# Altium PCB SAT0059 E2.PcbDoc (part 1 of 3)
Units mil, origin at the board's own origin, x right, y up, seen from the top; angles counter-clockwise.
Board outline 3960.27 x 3100.03 mil, 6 copper layers (Top Layer, GND, Power, Inner Routing, GND 2, Bottom Layer), stack 59.2 mil thick; 276 components, 209 nets, 812 pads, 621 vias.
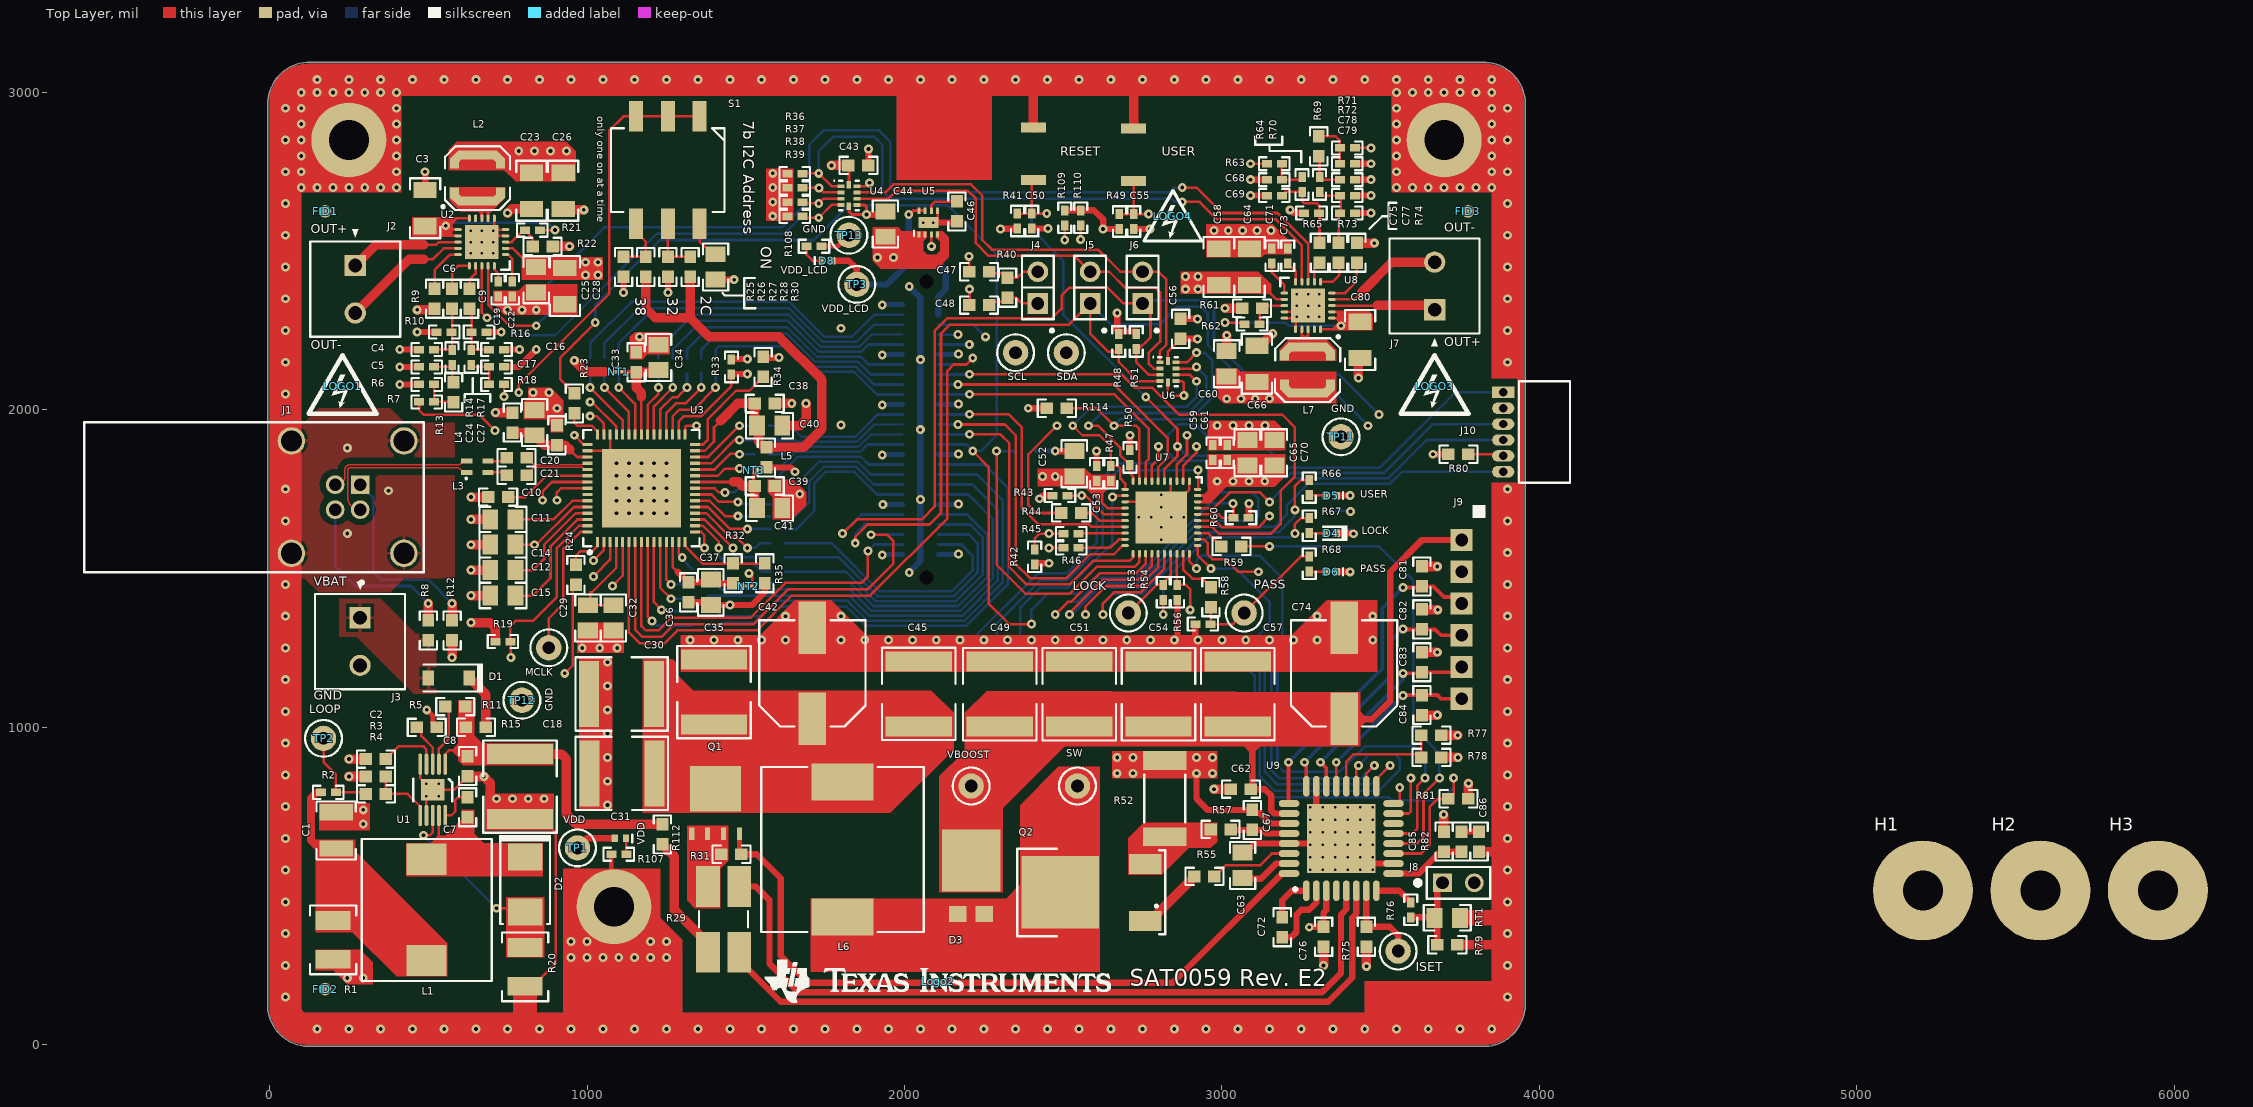
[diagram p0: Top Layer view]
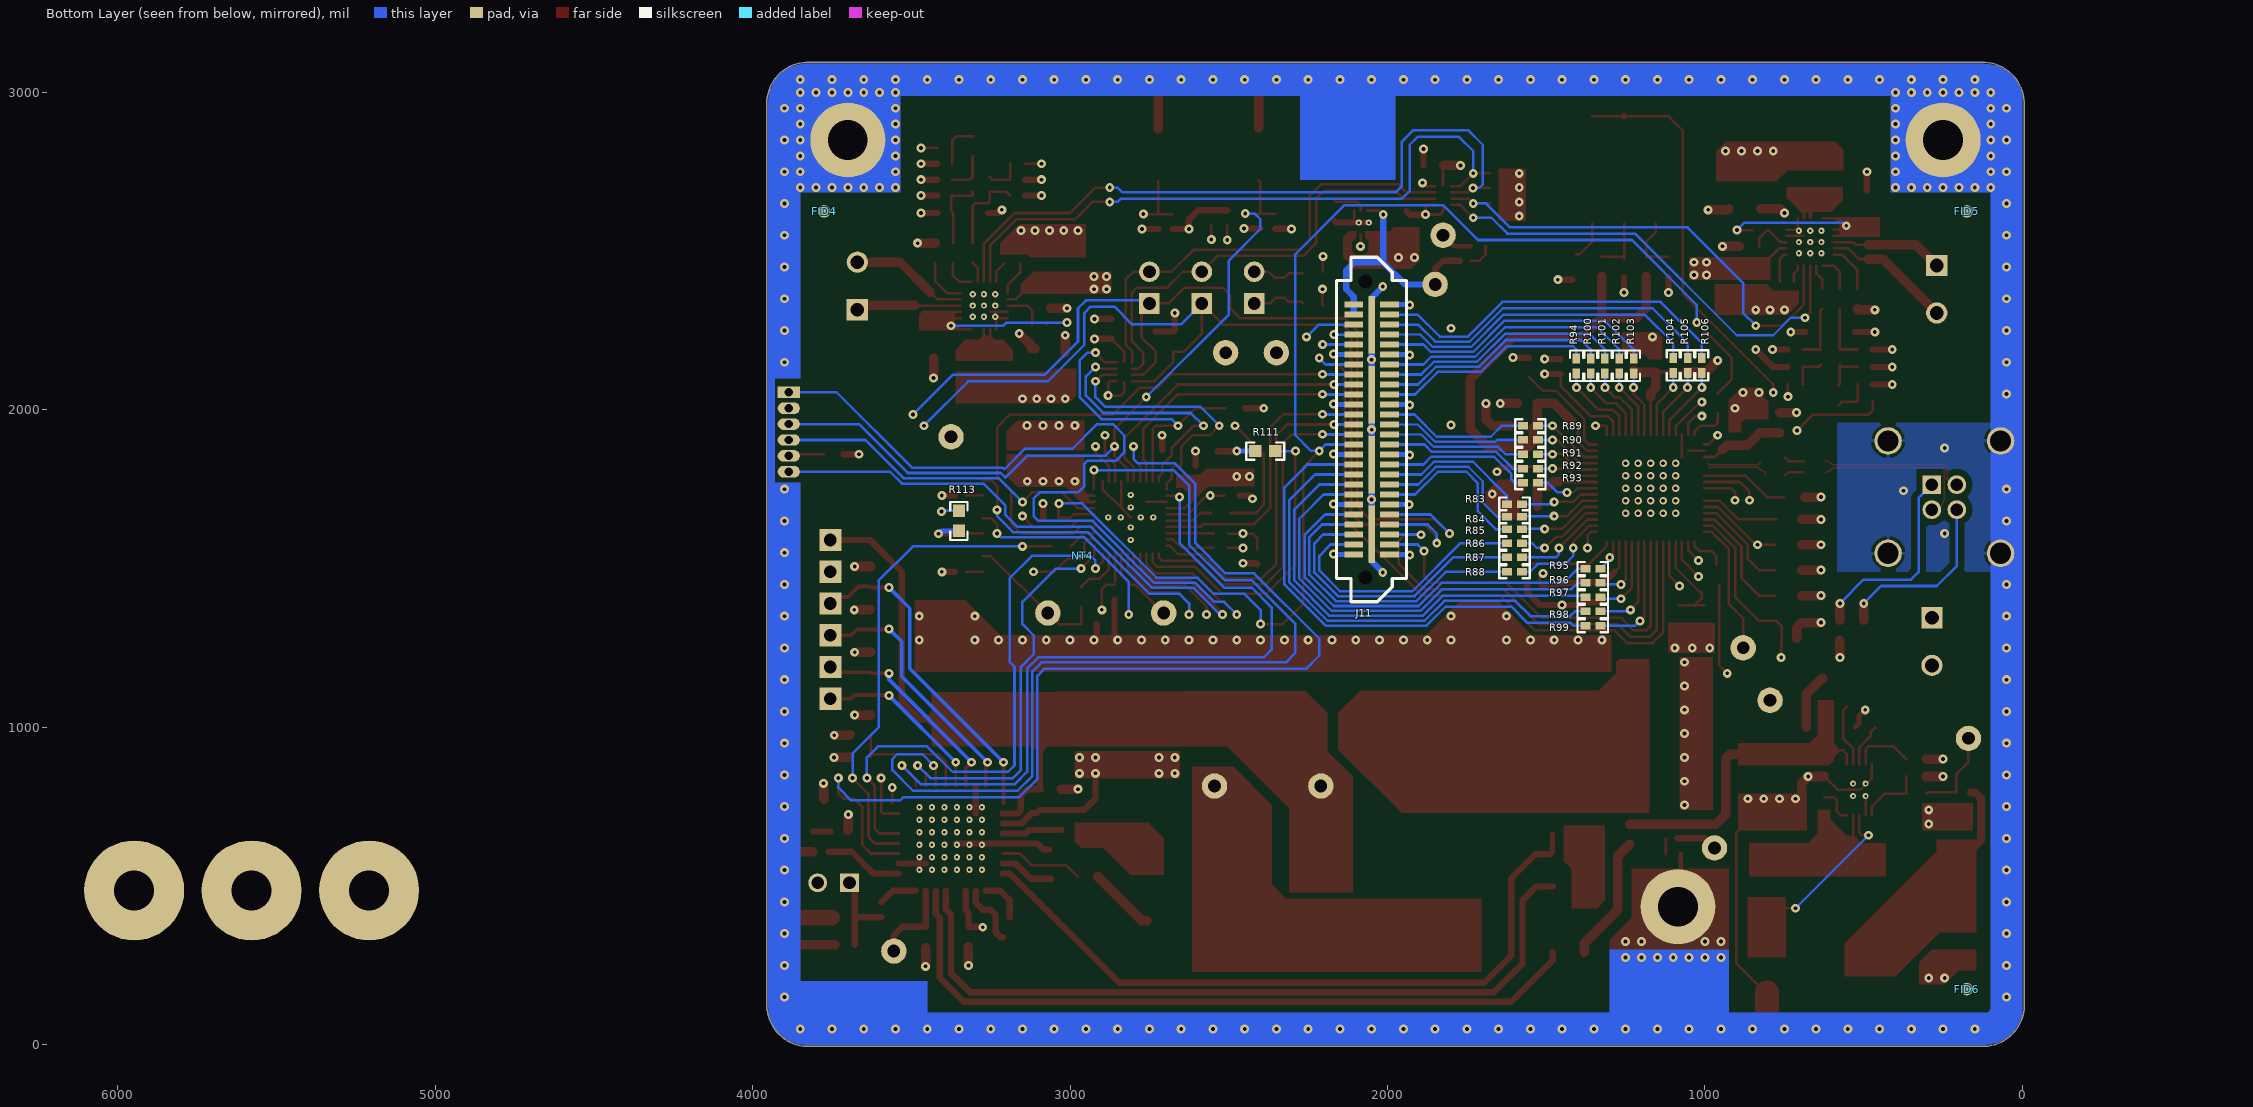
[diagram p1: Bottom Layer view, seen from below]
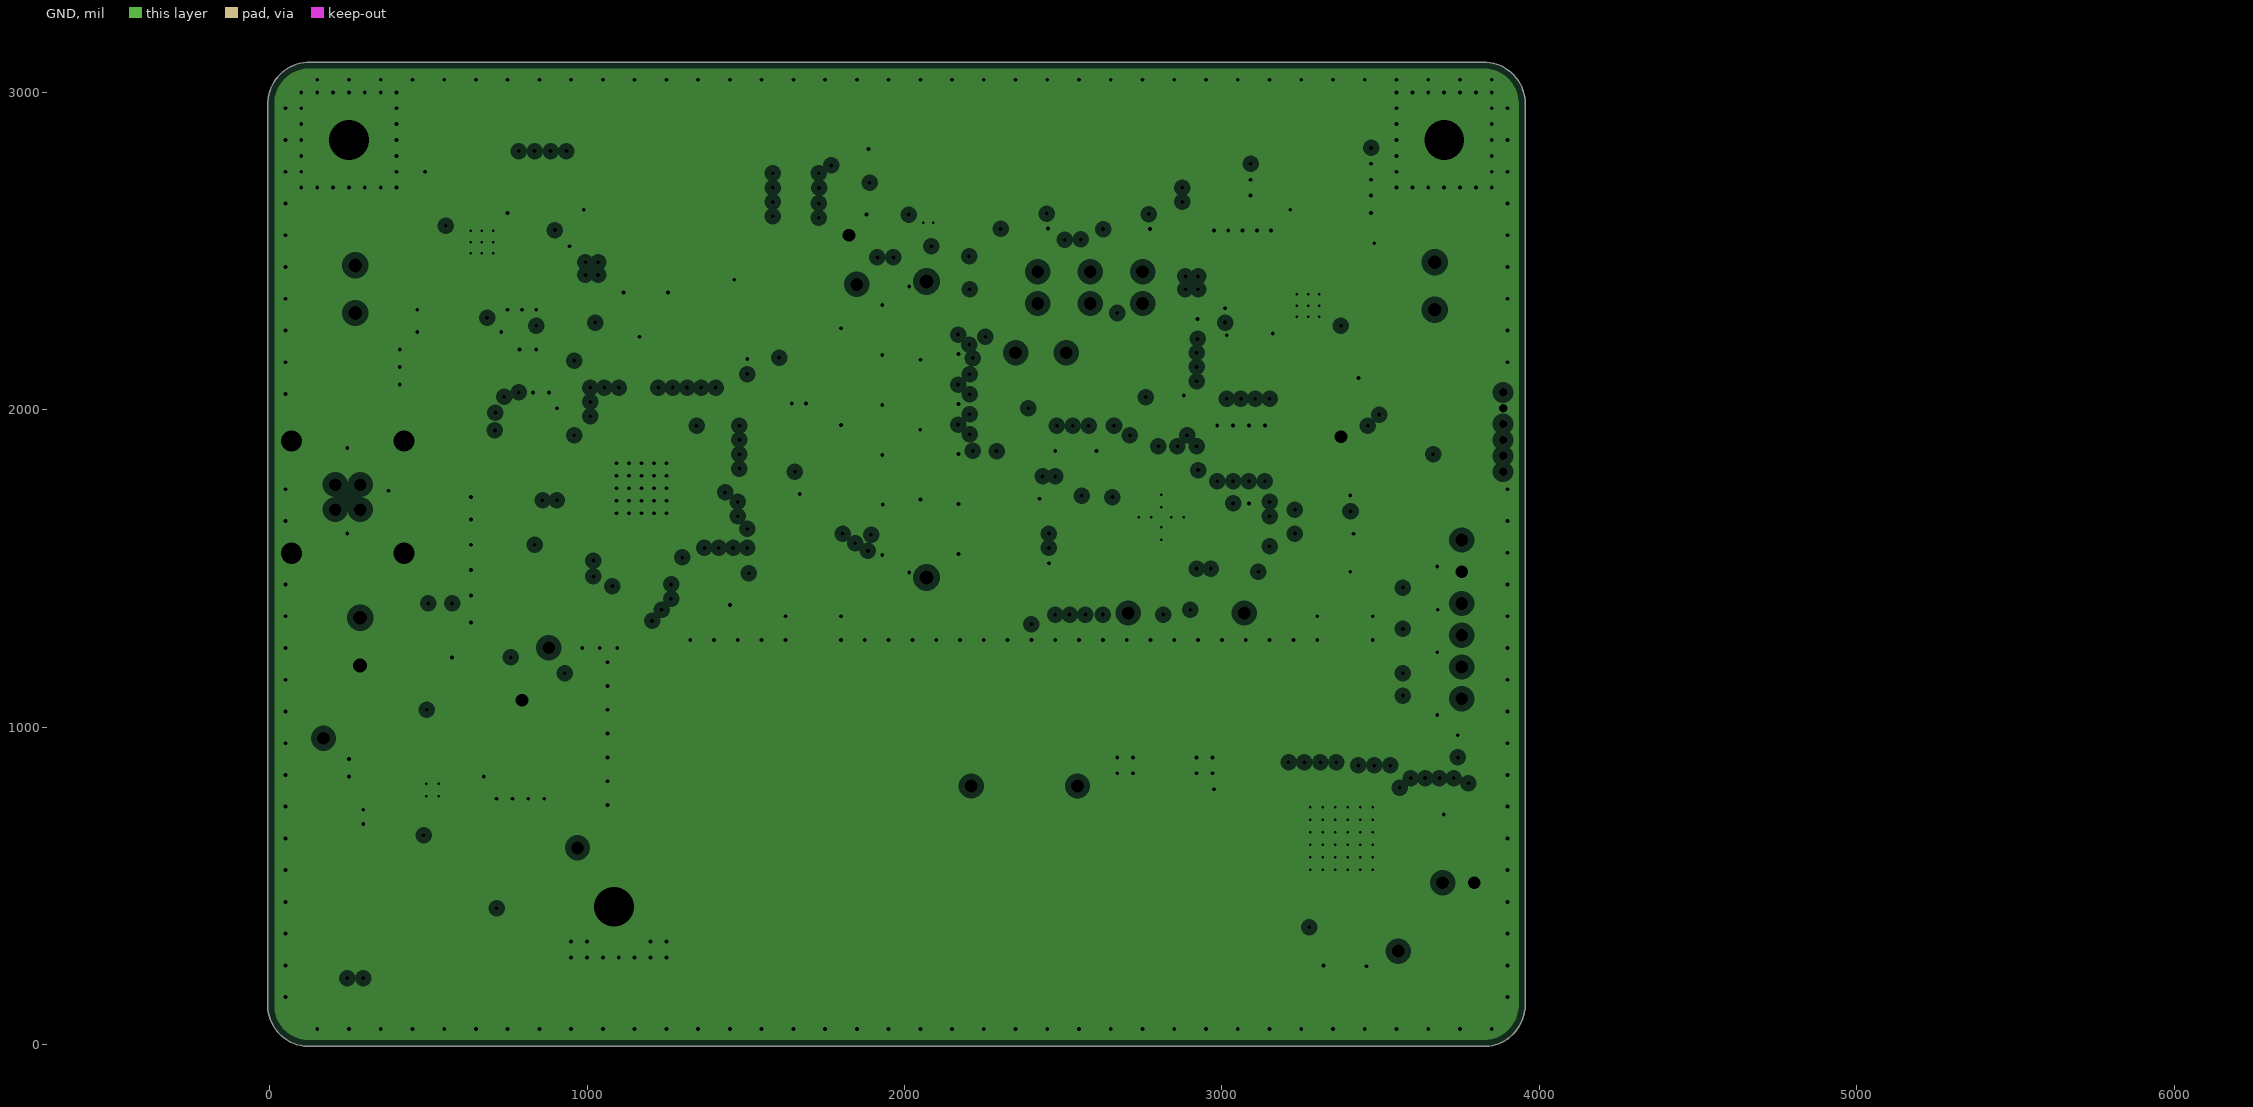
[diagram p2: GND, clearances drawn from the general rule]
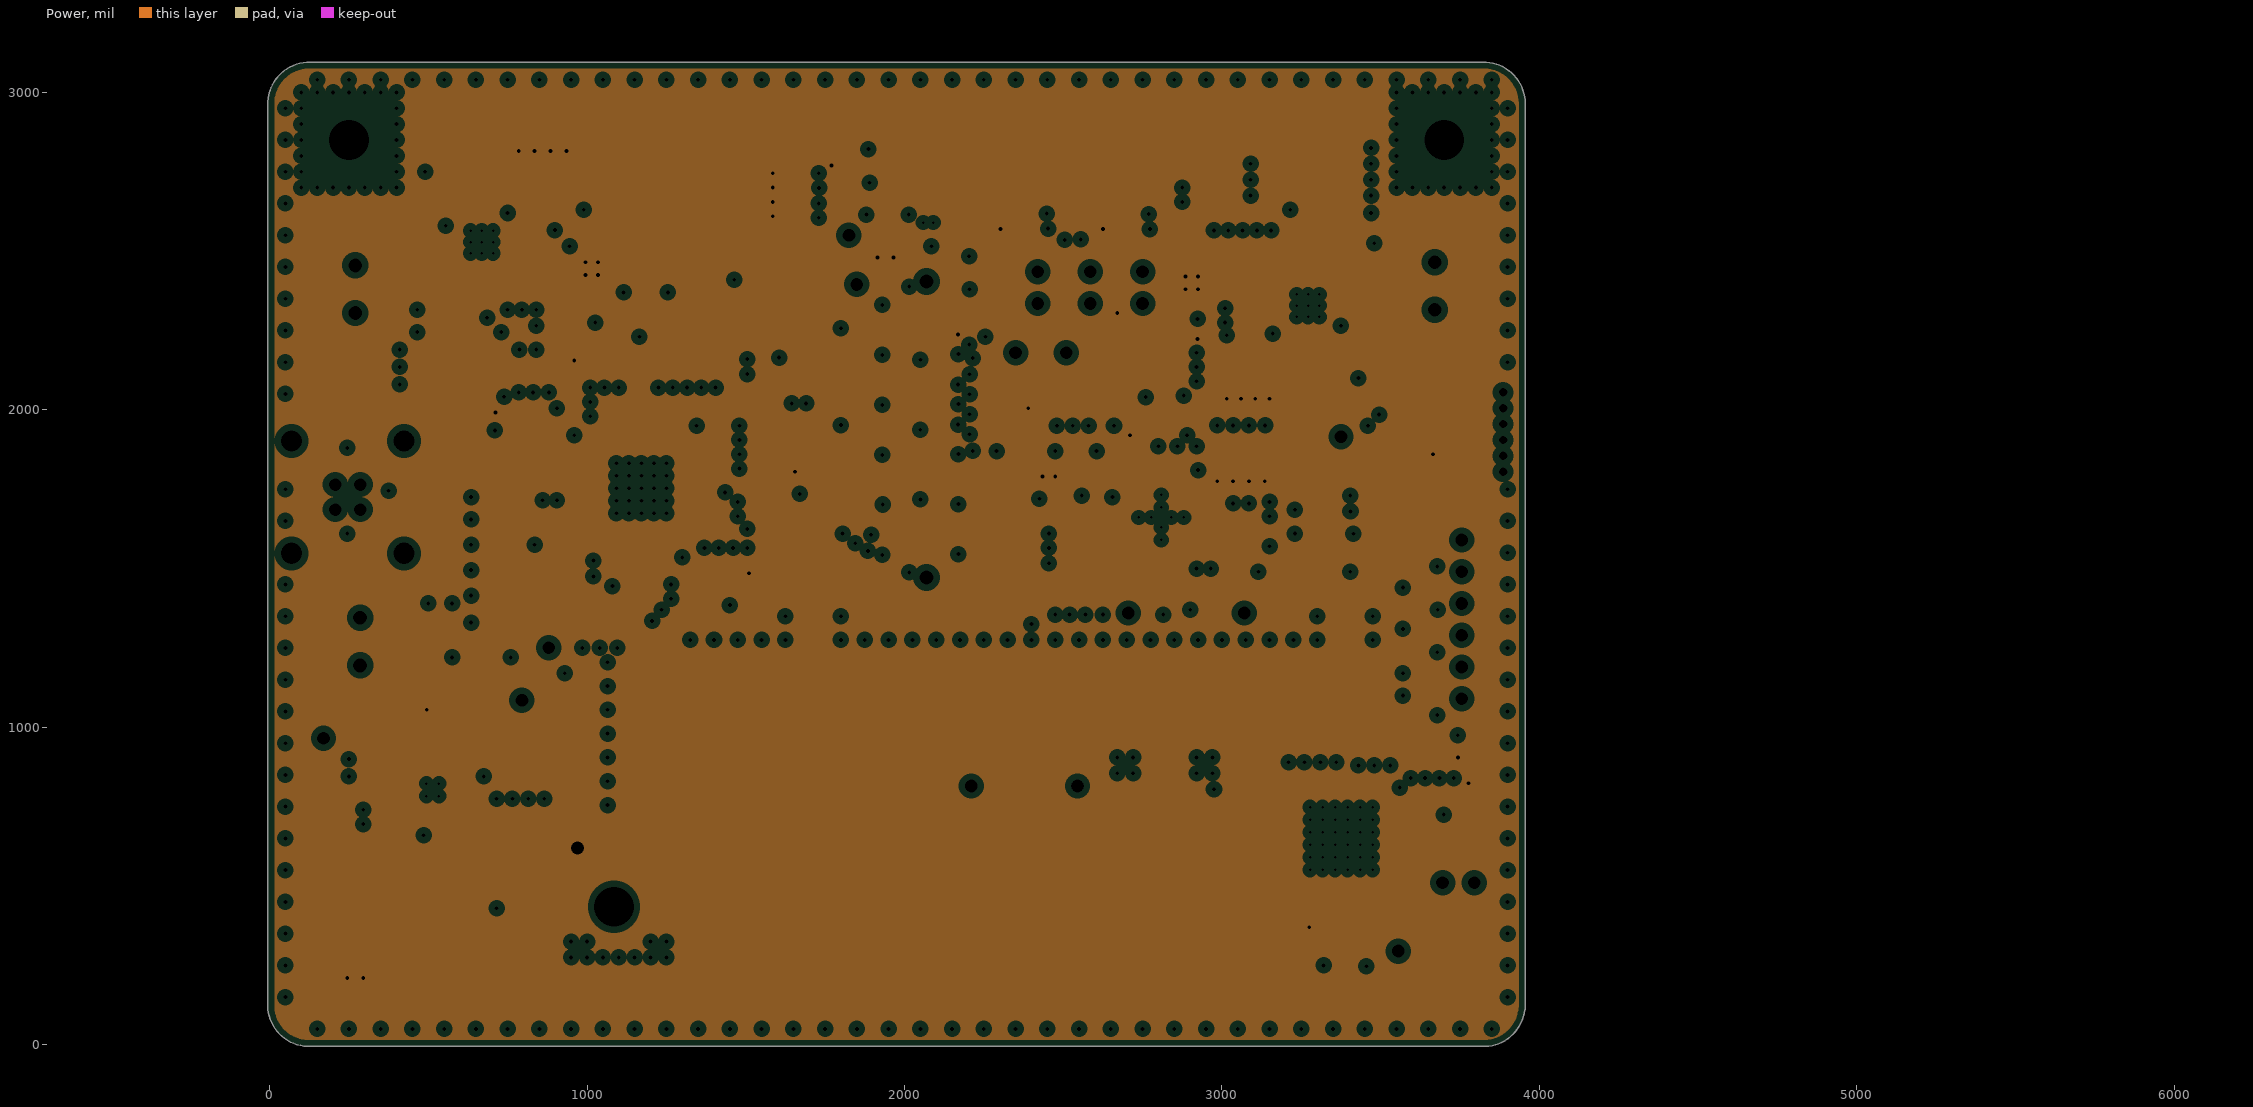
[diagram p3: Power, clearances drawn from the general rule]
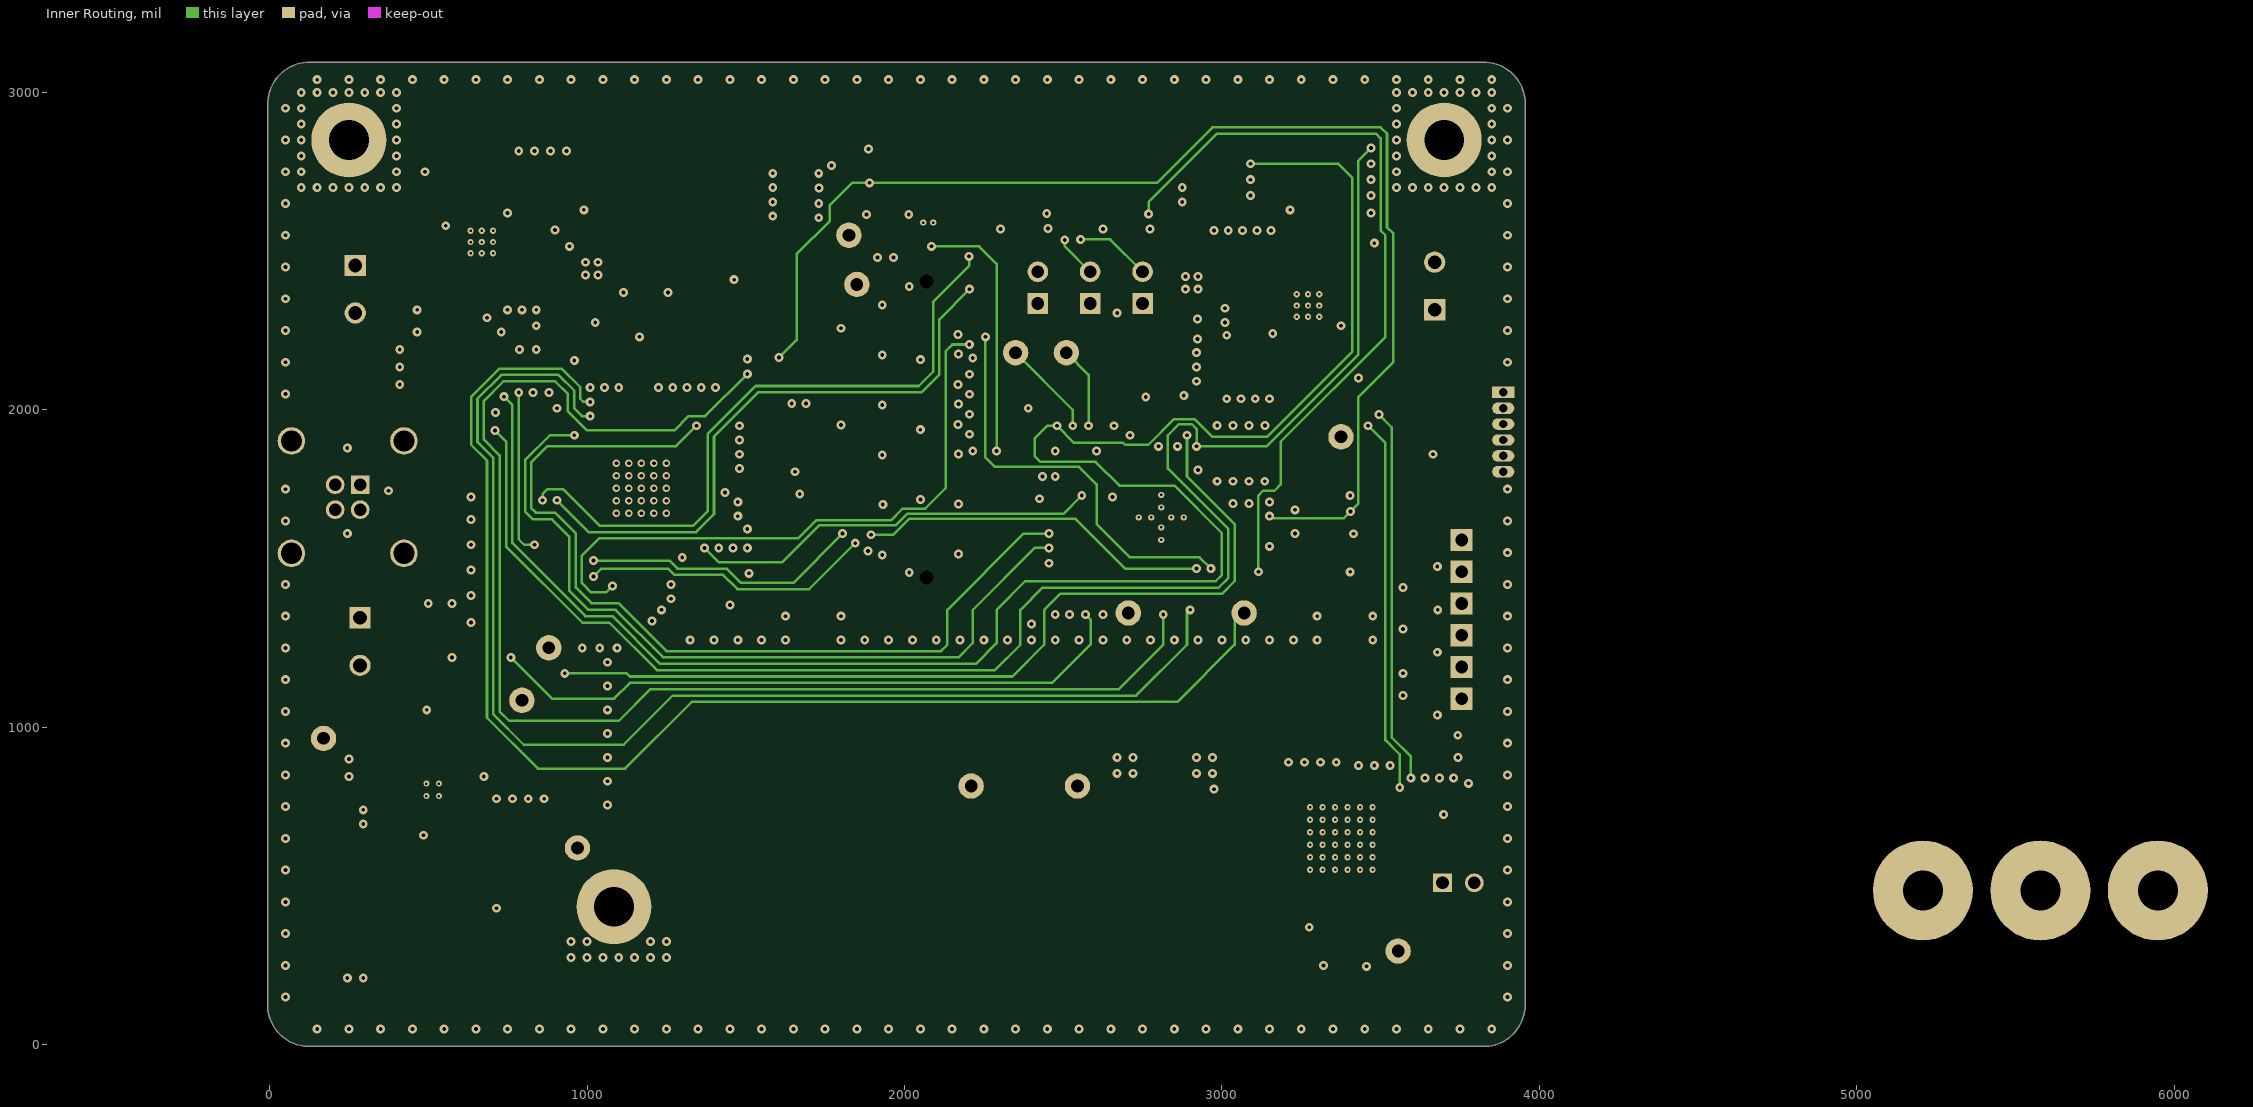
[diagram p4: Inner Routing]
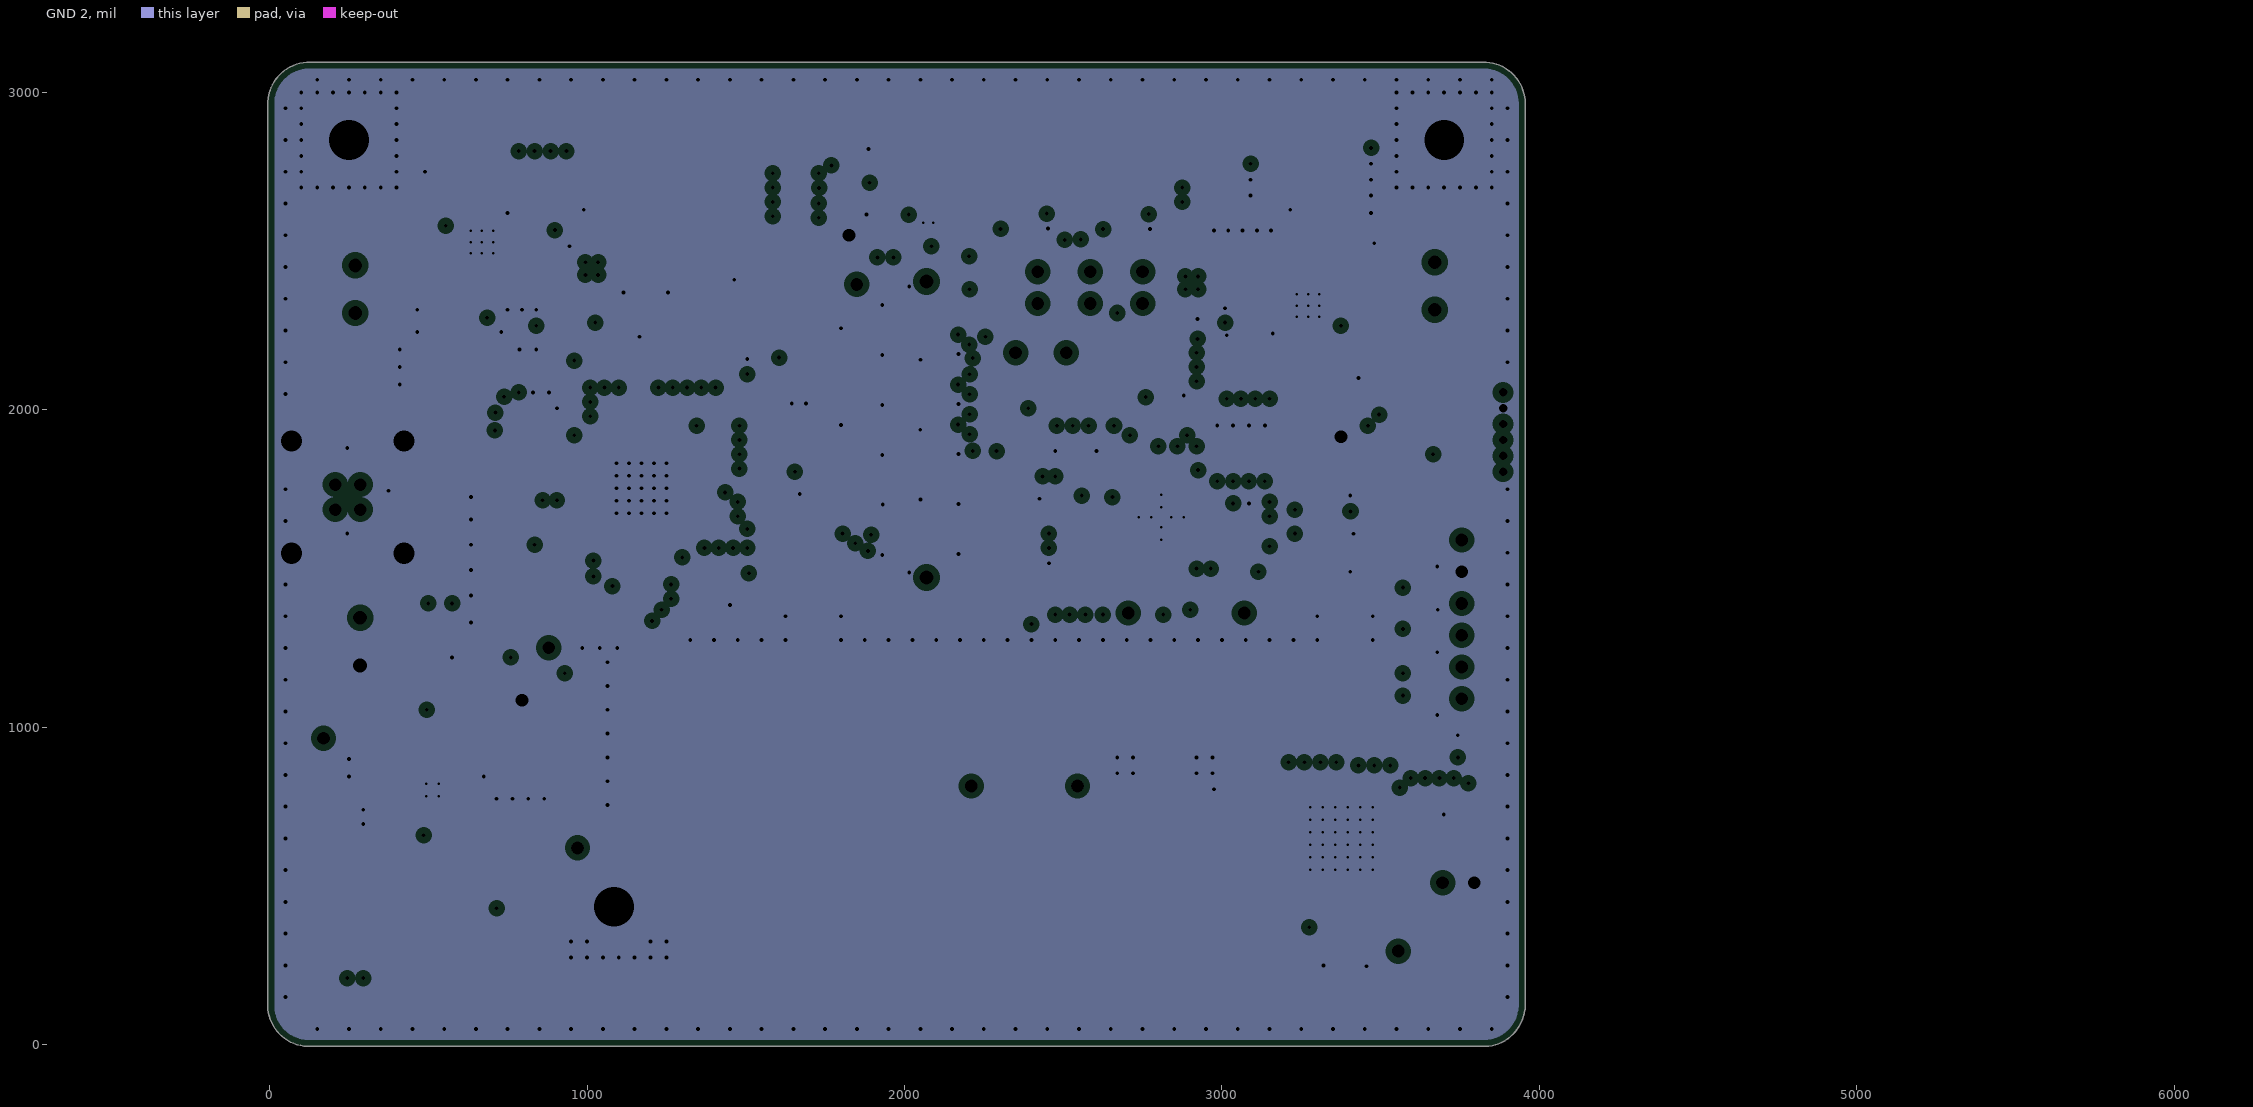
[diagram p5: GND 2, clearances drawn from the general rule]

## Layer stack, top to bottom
Top Layer: signal copper 1.4
Dielectric: core 5.2, 370HR, Dk 4.8
GND: plane copper 1.4, net GND
Dielectric: prepreg 5.2, 370HR, Dk 4.8
Power: plane copper 1.4, net VDD
Dielectric: core 30, 370HR, Dk 4.8
Inner Routing: signal copper 1.4
Dielectric: prepreg 5.2, 370HR, Dk 4.8
GND 2: plane copper 1.4, net GND
Dielectric: core 5.2, 370HR, Dk 4.8
Bottom Layer: signal copper 1.4

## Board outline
-5.01,113.48 -5.01,2958.89 cw(c124.87,2964.73) 128.26,3094.7 cw(c130,3090) 130,3095.02 3820,3095.02 cw(c3820,3090) 3821.74,3094.7 cw(c3825.13,2964.73) 3955.15,2964.73 cw(c3825.13,2964.73) 3955.02,2958.89 3955.02,112.6 cw(c3950,112.6) 3953.82,109.34 cw(c3824.73,124.87) 3818.89,-5.02 130.11,-5.02 cw(c124.27,124.87) -5.1,111.93 cw(c-0.11,112.43)

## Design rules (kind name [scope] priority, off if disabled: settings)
AcuteAngle [All] p1: minimum=4.50000000000000E+0001 checktracksonly=FALSE
AssemblyTestPointUsage [All] p1: valid=2
Clearance "DQD0016A u12" [IsTrack vs (OnLayer('Bottom Layer'))] p1: gap=7.5
Clearance DQD0016A [(InComponent('U10')) or (InComponent('U11')) or (InComponent('U12'))] p2: gap=7
Clearance differential [InNet('RIN_N') vs InNet('RIN_P')] p3: gap=4
Clearance "differential _1" [InNet('NetC21_1') vs InNet('NetC20_1')] p4: gap=4
Clearance Clearance_2 [InNet('RIN_N')] p5: gap=7
Clearance Clearance_1 [InComponent('J1')] p6: gap=5
Clearance "Clearance U6" [InComponent('U6')] p7: gap=6.8
Clearance "Clearance U4" [InComponent('U4')] p8: gap=6.8
Clearance "Clearance U1" [InComponent('U1') or InComponent('U12')] p9: gap=7.8
Clearance Clearance_BoardEdge_MountingHoles [OnCopper and InComponentClass('Mounting Holes') vs IsKeepOut] p10: gap=40
Clearance Clearance_BoardEdge_Poly [OnCopper and InPoly vs IsKeepOut] p11: gap=25
Clearance Clearance_BoardEdge [OnCopper and Not InComponentClass('Logo') and not InComponentClass('FiducialMark') and not InRegion(1000,500,4000,800) and Not IsKeepout vs IsKeepOut] p12: gap=75
Clearance Clearance_Poly [InPolygon] p13: gap=20
Clearance [All] p14: gap=8
ComponentClearance ComponentClearance_Logo [InComponentClass(Logo)] p1 off: gap=50 collisioncheckmode=3 verticalgap=10 showdistances=FALSE
ComponentClearance ComponentClearance_ScrewToNut [(HasFootprint('NY PMS 440 0025 PH')) vs (HasFootprint('Keystone_1902C'))] p2 off: gap=5 collisioncheckmode=3 verticalgap=10 showdistances=FALSE
ComponentClearance ComponentClearance_MountingHoles [InComponentClass('Mounting Holes')] p3 off: gap=250 collisioncheckmode=3 verticalgap=100000 showdistances=FALSE
ComponentClearance ComponentClearance_SmallPassives [HasFootprint('0201*') or HasFootprint('0402*') or HasFootprint('0508') or HasFootprint('0603*') or HasFootprint('0612') or HasFootprint('0805*') or HasFootprint('0815*') or HasFootprint('0830*') or HasFootprint('1206*') or HasFootprint('1210*') or HasFootprint('1808*') or HasFootprint('1812*') or HasFootprint('1825*') or HasFootprint('2010*') or HasFootprint('2220*') or HasFootprint('2225*') or HasFootprint('2512*') or HasFootprint('2728*') or HasFootprint('3518*') vs HasFootprint('0201*') or HasFootprint('0402*') or HasFootprint('0508') or HasFootprint('0603*') or HasFootprint('0612') or HasFootprint('0805*') or HasFootprint('0815*') or HasFootprint('0830*') or HasFootprint('1206*') or HasFootprint('1210*') or HasFootprint('1808*') or HasFootprint('1812*') or HasFootprint('1825*') or HasFootprint('2010*') or HasFootprint('2220*') or HasFootprint('2225*') or HasFootprint('2512*') or HasFootprint('2728*') or HasFootprint('3518*')] p4 off: gap=20 collisioncheckmode=3 verticalgap=10 showdistances=FALSE
ComponentClearance ComponentClearance_THtoSMT [IsThruComponent vs IsSMTComponent] p5 off: gap=100 collisioncheckmode=3 verticalgap=100000 showdistances=FALSE
ComponentClearance ComponentClearance_THtoTH [IsThruComponent vs IsThruComponent] p6 off: gap=118.11 collisioncheckmode=3 verticalgap=100000 showdistances=FALSE
ComponentClearance [All] p7 off: gap=40 collisioncheckmode=3 verticalgap=10 showdistances=FALSE
DiffPairsRouting [All] p1: maxlimit=100 minlimit=4 mostfreqgap=10 midlayer2_mingap=10 bottomlayer_mingap=10 maxuncoupledlength=1000
FabricationTestPointUsage TestPointUsage [All] p1: valid=2 allowmultiple=FALSE
FabricationTestpoint Testpoint [All] p1: side=3 testpointundercomponent=TRUE minsize=40 maxsize=100 preferedsize=60 minholesize=0 maxholesize=40 preferedholesize=32 testpointgrid=1 allowsidetop=TRUE allowsidebottom=TRUE usegrid=TRUE gridtolerance=0.01
FanoutControl Fanout_LCC [IsLCC] p1: bgadir=Out bgaviamode=Centered fanoutstyle=Auto fanoutdirection=Alternating viagrid=1 // Fanout_LCC (Default Rule)
FanoutControl Fanout_BGA [IsBGA] p2: bgadir=Out bgaviamode=Centered fanoutstyle=Auto fanoutdirection=Alternating viagrid=1 // Fanout_BGA (Default Rule)
FanoutControl Fanout_Default [All] p4: bgadir=Out bgaviamode=Centered fanoutstyle=Auto fanoutdirection=Alternating viagrid=1 // Fanout_Default (Default Rule)
FanoutControl Fanout_Small [(CompPinCount < 5)] p5: bgadir=Out bgaviamode=Centered fanoutstyle=Auto fanoutdirection=OutThenIn viagrid=1 // Fanout_Small (Default Rule)
HoleSize [All] p1: absolutevalues=TRUE maxlimit=251 minlimit=7.8 maxpercent=80.000 minpercent=20.000
MinimumAnnularRing [All] p1: minimumring=5
MinimumSolderMaskSliver MinimumSolderMaskSliver_Logo [InComponentClass('Logo') vs InComponentClass('Logo')] p1: minsoldermaskwidth=0.7
MinimumSolderMaskSliver [All] p2: minsoldermaskwidth=0
PlaneClearance [All] p1: clearance=20
PlaneConnect Via_Plane [Viasize] p1: planeconnectstyle=Direct reliefexpansion=20 reliefentries=4 reliefconductorwidth=10 reliefairgap=10
PlaneConnect [All] p2: planeconnectstyle=Relief reliefexpansion=10 reliefentries=4 reliefconductorwidth=10 reliefairgap=10
PolygonConnect Via_Polygon [Viasize] p1: connectstyle=Direct reliefconductorwidth=10 reliefentries=4 polygonreliefangle="90 Angle" airgapwidth=10
PolygonConnect [All] p2: connectstyle=Relief reliefconductorwidth=10 reliefentries=4 polygonreliefangle="90 Angle" airgapwidth=10
RoutingVias [All] p1: holewidth=16 width=34 viastyle="Through Hole" minholewidth=5 minwidth=18 maxholewidth=40 maxwidth=65
SMDToCorner [All] p1: distance=30000
SilkToSilkClearance [All] p1: silktosilkclearance=4
SilkscreenOverComponentPads [All] p1: minsilkscreentomaskgap=4
SolderMaskExpansion [All] p1: expansion=3
Width [All] p1: maxlimit=100 minlimit=5 preferedwidth=10 midlayer2_minwidth=6 bottomlayer_minwidth=6 minimp=50.000000 maximp=50.000000 favimp=50.000000 checkconnectedcopper=TRUE
13 further rules are at their usual default settings.

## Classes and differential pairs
component class "Mounting Holes": H1 H2 H3
component class "Power Supplies": C1 C2 C7 C8 C18 C44 C46 D1 D2 D8 J3 L1 R1 R2 R3 R4 R5 R11 R15 R20 R107 R108 R111 TP2 TP3 TP6 TP11 TP12 TP13 U1 U5 VDD
component class MCU: C50 C52 C53 C55 C56 C59 C61 C65 C70 D4 D5 D6 J5 J6 J10 LOCK NT4 PASS R33 R41 R43 R44 R45 R46 R47 R48 R49 R50 R51 R53 R54 R56 R58 R59 R60 R66 R67 R68 R80 R109 R110 R114 RESET SCL SDA U6 U7 USER
component class "LED Driver": C30 C31 C35 C42 C45 C49 C51 C54 C57 C62 C63 C67 C72 C74 C76 C81 C82 C83 C84 C85 C86 D3 ISET J8 J9 L6 Q1 Q2 R29 R31 R52 R55 R57 R75 R76 R77 R78 R79 R81 R82 R112 RT1 SW U9 VBOOST
component class Header: J5 J6
component class "Haptic Drivers": C3 C4 C5 C6 C9 C16 C17 C19 C22 C23 C25 C26 C28 C43 C58 C60 C64 C66 C68 C69 C71 C73 C75 C77 C78 C79 C80 J2 J7 L2 L7 R6 R7 R9 R10 R13 R14 R16 R17 R18 R21 R22 R36 R37 R38 R39 R61 R62 R63 R64 R65 R69 R70 R71 R72 R73 R74 R113 U2 U4 U8
component class Deserializer: C10 C11 C12 C14 C15 C20 C21 C24 C27 C29 C32 C33 C34 C36 C37 C38 C39 C40 C41 C47 C48 J4 L3 L4 L5 MCLK NT1 NT2 NT3 R19 R23 R24 R25 R26 R27 R28 R30 R32 R34 R35 R40 R42 R83 R84 R85 R86 R87 R88 R89 R90 R91 R92 R93 R94 R95 R96 R97 R98 R99 R100 R101 R102 R103 R104 R105 R106 S1 U3
component class Connectors: J1 J11 R8 R12
component class Logo: Logo2
component class Hardware: FID1 FID2 FID3 FID4 FID5 FID6 H1 H2 H3 LOGO1 Logo2 LOGO3 ZZ1 ZZ2 ZZ3 ZZ4 ZZ5
component class FiducialMark: FID1 FID2 FID3 FID4 FID5 FID6
component class AssemblyNote: ZZ1 ZZ2 ZZ3 ZZ4 ZZ5

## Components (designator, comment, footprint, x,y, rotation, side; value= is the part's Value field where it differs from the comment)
C1 "C3225X7R1C226M" 1210 210,675 r90 top
C2 "C1608X7R1H104K" 0603 335,900 r180 top
C3 "GRM31CR72E104KW03L" 1206 490,2635 r90 top
C4 "C1005X7R1C473K" 0402 495,2190 r180 top
C5 "C1005X7R1C473K" 0402 495,2135 r180 top
C6 "0603YC104JAT2A" 0603 575,2350 r270 top
C7 "C1608X7R1H104K" 0603 624,748 r90 top
C8 "C1608X7R1H104K" 0603 624,878 r270 top
C9 "0603YC104JAT2A" 0603 630,2350 r270 top
C10 "GCM188R71H104KA57B" 0603 720,1725 r180 top
C11 "EMK212BJ475KG-T" 0805_HV 735,1655 r180 top
C12 "GRM21BR71A475KA73L" 0805_HV 735,1495 r180 top
C14 "GCM188R71H104KA57B" 0805_HV 735,1575 r180 top
C15 "GRM21BR71A475KA73L" 0805_HV 735,1415 r180 top
C16 "C1005X7R1C473K" 0402 715,2190 r0 top
C17 "C1005X7R1C473K" 0402 715,2135 r0 top
C18 "C5750X7R1H106M" 2220 789,813 r270 top
C19 "GRM155R61C104KA88D" 0402 720,2380 r270 top
C20 "GCM188R71H104KA57B" 0603 778,1849 r180 top
C21 "GCM188R71H104KA57B" 0603 778,1794 r180 top
C22 "GRM155R61C104KA88D" 0402 765,2380 r270 top
C23 "12061C104KAT2A" 1206 825,2690 r270 top
C24 "GRM21BR71A475KA73L" 0805_HV 835,1960 r90 top
C25 "C0805C225K4RACTU" 0805_HV 840,2410 r270 top
C26 "12061C104KAT2A" 1206 925,2690 r270 top
C27 "0603YC104JAT2A" 0603 905,1920 r90 top
C28 "12061C104KAT2A" 1206 930,2390 r270 top
C29 "GRM21BR71A475KA73L" 0805_HV 1003,1344.5 r270 top
C30 "C5750X7S2A106M" 2220 1109.15,1104.81 r180 top
C31 "C5750X7S2A106M" 2220 1109.47,854.81 r180 top
C32 "GRM21BR71A475KA73L" 0805_HV 1083,1344.5 r270 top
C33 "0603YC104JAT2A" 0603 1155,2150 r90 top
C34 "GRM21BR71A475KA73L" 0805_HV 1225,2165 r90 top
C35 "C5750X7S2A106M" 2220 1399.81,1110.85 r90 top
C36 "0603YC104JAT2A" 0603 1320,1425 r270 top
C37 "GRM21BR71A475KA73L" 0805_HV 1390,1425 r270 top
C38 "0603YC104JAT2A" 0603 1560,2020 r0 top
C39 "0603YC104JAT2A" 0603 1560,1760 r0 top
C40 "GRM21BR71A475KA73L" 0805_HV 1575,1950 r0 top
C41 "GRM21BR71A475KA73L" 0805_HV 1575,1690 r0 top
C42 "EMZA630ADA470MHA0G" CAPSMT_62_HA0 1710,1170 r90 top
C43 "0603YC104JAT2A" 0603 1855,2770 r0 top
C44 "EMK212BJ475KG-T" 0805_HV 1940,2585 r90 top
C45 "C5750X7S2A106M" 2220 2045,1105 r90 top
C46 "06035A221JAT2A" 0603 2165,2625 r270 top
C47 "GCM188R71H104KA57B" 0603 2235,2435 r0 top
C48 "GCM188R71H104KA57B" 0603 2235,2330 r0 top
C49 "C5750X7S2A106M" 2220 2300.19,1104.15 r90 top
C50 "UMK105B7222KV-F" 0402 2401,2594.64 r270 top
C51 "C5750X7S2A106M" 2220 2550.19,1104.15 r90 top
C52 "GRM21BR71A106KE51L" 0805_HV 2535,1830 r90 top
C53 "C1005X5R1A104K" 0402 2605,1800 r90 top
C54 "C5750X7S2A106M" 2220 2800.19,1104.15 r90 top
C55 "UMK105B7222KV-F" 0402 2722,2593 r270 top
C56 "0603YC104JAT2A" 0603 2870,2255 r90 top
C57 "C5750X7S2A106M" 2220 3050.19,1104.47 r90 top
C58 "12061C104KAT2A" 1206 2990,2450 r90 top
C59 "C1005X5R1A104K" 0402 2971.81,1865 r90 top
C60 "C0805C225K4RACTU" 0805_HV 3015,2145 r90 top
C61 "C1005X5R1A104K" 0402 3016.81,1865 r90 top
C62 "GRM1885C2A470JA01D" 0603 3060,805 r180 top
C63 "GRM21BR61C106KE15L" 0805_HV 3065,565 r90 top
C64 "12061C104KAT2A" 1206 3087.36,2450 r90 top
C65 "GRM21BR71A106KE51L" 0805_HV 3080,1865 r90 top
C66 "12061C104KAT2A" 1206 3110,2145 r90 top
C67 "GRM188R72A102KA01D" 0603 3095.63,708.11 r270 top
C68 "C1005X7R1C473K" 0402 3165,2725 r180 top
C69 "C1005X7R1C473K" 0402 3165,2675 r180 top
C70 "GRM21BR71A106KE51L" 0805_HV 3165,1865 r90 top
C71 "GRM155R61C104KA88D" 0402 3157.36,2485 r90 top
C72 "GRM188R71E105KA12D" 0603 3190,370 r90 top
C73 "GRM155R61C104KA88D" 0402 3207.36,2485 r90 top
C74 "EMZA630ADA470MHA0G" CAPSMT_62_HA0 3385,1170 r90 top
C75 "0603YC104JAT2A" 0603 3307.36,2495 r90 top
C76 "GRM188R71E105KA12D" 0603 3320,340 r90 top
C77 "0603YC104JAT2A" 0603 3367.36,2495 r90 top
C78 "C1005X7R1C473K" 0402 3395,2725 r0 top
C79 "C1005X7R1C473K" 0402 3395,2675 r0 top
C80 "GRM31CR72E104KW03L" 1206 3435,2220 r270 top
C81 "06031C222JAT2A" 0603 3630,1475 r90 top
C82 "06031C222JAT2A" 0603 3630,1340 r90 top
C83 "06031C222JAT2A" 0603 3630,1205 r90 top
C84 "06031C222JAT2A" 0603 3630,1070 r270 top
C85 "C1608C0G1E472J" 0603 3700,640 r90 top
C86 "GRM188R71C393KA01D" 0603 3810,640 r270 top
D1 "1N5819HW-7-F" SOD-123 565,1155 r180 top
D2 "MBRS260T3G" SMB 805,505 r270 top
D3 "D_SCHOT_SS5P10_" TO-277[SMPC] 2210,580 r0 top
D4 "SML-P12MTT86" SML-P1_YELLOW-GREEN 3343.76,1611.24 r0 top
D5 "SML-P12YTT86" LED_SMLP12_Yellow 3345,1730 r0 top
D6 "SML-P12DTT86" LED_SMLP12_ORANGE 3345,1490 r0 top
D8 "SML-P12PTT86" SML-P1_GREEN 1755,2470 r0 top
FID1 "Fiducial" Fiducial10-20 175,2625 r0 top
FID2 "Fiducial" Fiducial10-20 175,175 r0 top
FID3 "Fiducial" Fiducial10-20 3775,2625 r0 top
FID4 "Fiducial" Fiducial10-20 3775,2625 r180 bottom
FID5 "Fiducial" Fiducial10-20 175,2625 r180 bottom
FID6 "Fiducial" Fiducial10-20 175,175 r180 bottom
H1 "NY PMS 440 0025 PH" "NY PMS 440 0025 PH" 5208,486 r0 top
H2 "NY PMS 440 0025 PH" "NY PMS 440 0025 PH" 5578,486 r0 top
H3 "NY PMS 440 0025 PH" "NY PMS 440 0025 PH" 5948,486 r0 top
ISET "5000" Keystone5000 3555,295 r270 top (schematic designator TP6)
J1 "D4S20G-400A5-Z" Rosenberger_D4S20G-400A5 0,1725 r180 top
J2 "1727010" PhoenixConact_1727010 270,2380 r270 top
J3 "1727010" PhoenixConact_1727010 285,1270 r270 top
J4 "90120-0122" CONN_90120-0122 2420,2385 r90 top
J5 "TSW-102-07-G-S" TSW-102-07-G-S 2585,2385 r90 top
J6 "TSW-102-07-G-S" TSW-102-07-G-S 2750,2385 r90 top
J7 "1727010" PhoenixConact_1727010 3670,2390 r90 top
J8 "PEC02SAAN" CONN_PEC02SAAN 3745,510 r0 top
J9 "HEADER_HMTSW-106-07-X-230" HDR-100_1X6 3755,1590 r270 top
J10 "851-43-006-20-001000" CONN_851-43-006-20-001000 3886,1930 r90 top
J11 "QRM8-026-02.0-L-D-A" Samtec_QRM8-026-02.0-L-D-A 2050,1938 r270 bottom locked
L1 "SLF10145T-5R6M3R2-PF" SLF10145 495,425 r270 top
L2 "LPS4018-332MLB" LPS4018 655,2730 r90 top
L3 "DLW21SN900HQ2L" IND_DLW21S 655,1821 r90 top
L4 "BLM18SG121TN1D" 0603 765,1960 r90 top
L5 "BLM18SG121TN1D" 0603 1565,1850 r270 top
L6 "IHLP5050FDER220M5A" IHLP-5050FD 1805,615 r270 top
L7 "LPS4018-332MLB" LPS4018 3270,2125 r270 top
LOCK "5004" Keystone5004 2705,1360 r270 top (schematic designator TP10)
LOGO1 "DANGER HIGH VOLTAGE" IEC_HighVoltage_Small 230,2075 r0 top
Logo2 "Texas Instruments" TI_Horizontal_Overlay_Small 2105,200 r0 top
LOGO3 "DANGER HIGH VOLTAGE" IEC_HighVoltage_Small 3670,2075 r0 top
LOGO4 "DANGER HIGH VOLTAGE" IEC_HighVoltage_Small 2845,2610 r0 top (schematic designator LOGO3)
MCLK "5004" Keystone5004 879.75,1250.25 r0 top (schematic designator TP14)
NT1 "Net-Tie" Net-Tie_10mil 1100,2120 r0 top net-tie
NT2 "Net-Tie" Net-Tie_10mil 1510,1445 r180 top net-tie
NT3 "Net-Tie" Net-Tie_10mil 1525,1810 r270 top net-tie
NT4 "Net-Tie" Net-Tie_10mil 2960,1540 r180 bottom net-tie
PASS "5004" Keystone5004 3070,1360 r90 top (schematic designator TP9)
Q1 "SQJ461EP" PowerPAK_SO-8L 1405,775 r90 top
Q2 "IPD25N06S4L-30" DPAK 2625,480 r180 top
R1 "MCR25JZHJ000" 1210M 200,330 r270 top
R2 "CRCW040249R9FKED" 0402 185,795 r180 top
R3 "RC0603JR-075K1L" 0603 335,845 r0 top
R4 "RC0603JR-071K6L" 0603 335,790 r180 top
R5 "CRCW060310K0JNEA" 0603 495,1000 r180 top
R6 "CRCW04026K49FKED" 0402 495,2080 r0 top
R7 "CRCW04026K49FKED" 0402 495,2025 r180 top
R8 "CRCW06030000Z0EA" 0603 500,1305 r270 top
R9 "CRCW060313K0JNEA" 0603 520,2350 r90 top
R10 "CRCW04022K70JNED" 0402 550,2245 r0 top
R11 "CRCW060336K0JNEA" 0603 585,1065 r180 top
R12 "CRCW06030000Z0EA" 0603 575,1305 r90 top
R13 "CRCW06030000Z0EA" 0603 580,2055 r270 top
R14 "CRCW04023K30JNED" 0402 575,2165 r90 top
R15 "CRCW06030000Z0EA" 0603 650,1000 r0 top
R16 "CRCW04022K70JNED" 0402 660,2245 r180 top
R17 "CRCW04023K30JNED" 0402 635,2165 r90 top
R18 "CRCW04023K30JNED" 0402 715,2080 r180 top
R19 "CRCW040210K0JNED" 0402 735,1270 r0 top
R20 "ERJ14RSJR12U" 1210M 805,245 r90 top
R21 "CRCW0402768KFKED" 0402 827.5,2566 r0 top
R22 "CRCW060313K0JNEA" 0603 860,2515 r180 top
R23 "CRCW06030000Z0EA" 0603 960,2020 r270 top
R24 "CRCW06030000Z0EA" 0603 965,1480 r90 top
R25 "RC0603FR-0718KL" 0603 1115,2450 r90 top
R26 "CRCW060315K4FKEA" 0603 1185,2450 r270 top
R27 "CRCW06039K09FKEA" 0603 1255,2450 r90 top
R28 "CRCW060324K3FKEA" 0603 1325,2450 r270 top
R29 "LVK24R020FER" 2412 1430,395 r270 top
R30 "CRCW080540K2FKEA" 0805_HV 1405,2450 r90 top
R31 "CRCW060320K0FKEA" 0603 1455,600 r180 top
R32 "CRCW0603200RFKEA" 0603 1460,1485 r270 top
R33 "CRCW040210K0JNED" 0402 1455,2135 r270 top
R34 "CRCW0603100RFKEA" 0603 1555,2135 r270 top
R35 "CRCW060347K0JNEA" 0603 1560,1485 r90 top
R36 "CRCW040233K0JNED" 0402 1654.72,2743.99 r180 top
R37 "CRCW040233K0JNED" 0402 1654.72,2698.99 r180 top
R38 "CRCW040233K0JNED" 0402 1654.72,2653.99 r180 top
R39 "CRCW040233K0JNED" 0402 1654.72,2608.99 r180 top
R40 "CRCW0603100RFKEA" 0603 2325,2385 r90 top
R41 "CRCW040247K0JNED" 0402 2356,2594.64 r270 top
R42 "CRCW040210K0JNED" 0402 2410,1536.81 r90 top
R43 "CRCW040210K0JNED" 0402 2490,1730 r0 top
R44 "CRCW06030000Z0EA" 0603 2525,1675 r0 top
R45 "CRCW0402330RJNED" 0402 2525,1610 r180 top
R46 "CRCW0402330RJNED" 0402 2525,1565 r180 top
R47 "CRCW040233K0JNED" 0402 2650,1800 r270 top
R48 "CRCW040210K0JNED" 0402 2675,2215 r90 top
R49 "CRCW040247K0JNED" 0402 2677,2593 r270 top
R50 "CRCW040233K0JNED" 0402 2710,1850 r90 top
R51 "CRCW040210K0JNED" 0402 2730,2215 r90 top
R52 "CRA2512-FZ-R025ELF" 2512M 2820,775 r270 top
R53 "CRCW0402330RJNED" 0402 2815,1425 r90 top
R54 "CRCW040210K0JNED" 0402 2860,1425 r90 top
R55 "RC0603JR-070RL" 0603 2945,530 r0 top
R56 "CRCW040210K0JNED" 0402 2940,1325 r0 top
R57 "CRCW060310R0FKEA" 0603 2995.63,678.11 r180 top
R58 "CRCW06030000Z0EA" 0603 2965,1410 r270 top
R59 "CRCW06030000Z0EA" 0603 3030,1570 r0 top
R60 "CRCW040210K0JNED" 0402 3060,1660 r180 top
R61 "CRCW060313K0JNEA" 0603 3095,2320 r0 top
R62 "CRCW0402768KFKED" 0402 3095,2270 r180 top
R63 "CRCW04023K30JNED" 0402 3165,2775 r0 top
R64 "CRCW04023K30JNED" 0402 3252.36,2710 r270 top
R65 "CRCW04022K70JNED" 0402 3282.36,2620 r0 top
R66 "CRCW0402487RFKED" 0402 3275,1755 r90 top
R67 "CRCW0402220RJNED" 0402 3275,1635 r90 top
R68 "CRCW0402487RFKED" 0402 3275,1515 r90 top
R69 "CRCW06030000Z0EA" 0603 3305,2830 r90 top
R70 "CRCW04023K30JNED" 0402 3307.36,2710 r270 top
R71 "CRCW04026K49FKED" 0402 3395,2825 r0 top
R72 "CRCW04026K49FKED" 0402 3395,2775 r180 top
R73 "CRCW04022K70JNED" 0402 3395,2620 r180 top
R74 "CRCW060313K0JNEA" 0603 3425,2495 r270 top
R75 "RC0603FR-0712K4L" 0603 3455,340 r90 top
R76 "CRCW04023K00JNED" 0402 3595,425 r90 top
R77 "CRCW060310K0JNEA" 0603 3660,975 r0 top
R78 "CRCW060310K0JNEA" 0603 3660,905 r180 top
R79 "CRCW06032M00FKEA" 0603 3710,315 r0 top
R80 "CRCW06030000Z0EA" 0603 3745,1860 r180 top
R81 "CRCW060310K0JNEA" 0603 3745,775 r180 top
R82 "RC0603FR-07750KL" 0603 3755,640 r270 top
R83 "CRCW040249R9FKED" 0402 1600,1703.21 r0 bottom
R84 "CRCW040249R9FKED" 0402 1600,1663.21 r0 bottom
R85 "CRCW040249R9FKED" 0402 1600,1623.21 r0 bottom
R86 "CRCW040249R9FKED" 0402 1600,1580 r0 bottom
R87 "CRCW040249R9FKED" 0402 1600,1535 r0 bottom
R88 "CRCW040249R9FKED" 0402 1600,1490 r0 bottom
R89 "CRCW040249R9FKED" 0402 1550,1950 r0 bottom
R90 "CRCW040249R9FKED" 0402 1550,1905 r0 bottom
R91 "CRCW040249R9FKED" 0402 1550,1860 r0 bottom
R92 "CRCW040249R9FKED" 0402 1550,1815 r0 bottom
R93 "CRCW040249R9FKED" 0402 1550,1770 r0 bottom
R94 "CRCW040249R9FKED" 0402 1405,2138.62 r90 bottom
R95 "CRCW040249R9FKED" 0402 1353.19,1500 r0 bottom
R96 "CRCW040249R9FKED" 0402 1353.19,1455 r0 bottom
R97 "CRCW040249R9FKED" 0402 1353.19,1410 r0 bottom
R98 "CRCW040249R9FKED" 0402 1353.19,1365 r0 bottom
R99 "CRCW040249R9FKED" 0402 1353.19,1320 r0 bottom
R100 "CRCW040249R9FKED" 0402 1360,2138.62 r90 bottom
R101 "CRCW040249R9FKED" 0402 1315,2138.62 r90 bottom
R102 "CRCW040249R9FKED" 0402 1270,2138.62 r90 bottom
R103 "CRCW040249R9FKED" 0402 1225,2138.62 r90 bottom
R104 "CRCW040249R9FKED" 0402 1100,2140 r90 bottom
R105 "CRCW040249R9FKED" 0402 1055,2140 r90 bottom
R106 "CRCW040249R9FKED" 0402 1010,2140 r90 bottom
R107 "CRCW0402220RJNED" 0402 1100,600 r0 top
R108 "CRCW0402220RJNED" 0402 1715,2515 r180 top
R109 "CRCW040210K0JNED" 0402 2505,2605 r90 top
R110 "CRCW040210K0JNED" 0402 2555,2605 r90 top
R111 "CRCW060310K0JNEA" 0603 2385,1870 r0 bottom
R112 "RC0603JR-070RL" 0603 1237.5,662.5 r90 top
R113 "CRCW060310K0JNEA" 0603 3350,1650 r270 bottom
R114 "CRCW060310K0JNEA" 0603 2480,2005 r0 top
RESET "SKRKAEE010" SW_SKRKAEE010 2406,2806.02 r90 top (schematic designator S2)
RT1 "NCP21XQ102J03RA" 0805_HV 3710,400 r180 top
S1 "219-3LPST" SW_219-3LPST 1255,2755 r270 top
SCL "5004" Keystone5004 2350,2180 r0 top (schematic designator TP8)
SDA "5004" Keystone5004 2510,2180 r0 top (schematic designator TP7)
SW "5000" Keystone5000 2545,815 r0 top (schematic designator TP4)
TP1 "5000" Keystone5000 970,620 r0 top
TP2 "5004" Keystone5004 170,965 r270 top
TP3 "5000" Keystone5000 1850,2395 r0 top
TP11 "5001" Keystone5001 3375,1915 r0 top
TP12 "5001" Keystone5001 795,1085 r0 top
TP13 "5001" Keystone5001 1825,2550 r0 top
U1 "LM25011MY/NOPB" DGQ0010A_N 514,803 r270 top
U2 "DRV2667RGP" RGP0020D 668.5,2528.35 r180 top
U3 "DS90UH926QSQ/NOPB" DS90UH926QSQ/NOPB 1171.35,1753.01 r0 top locked
U4 "TS3USB221AQRSERQ1" RSE0010A 1825,2675 r0 top
U5 "TPS22965DSG" DSG0008A 2075,2590 r90 top
U6 "TS3USB221AQRSERQ1" RSE0010A 2830,2120 r0 top
U7 "MSP430F2252TRHA" RHA0040B 2809,1661 r270 top
U8 "DRV2667RGP" RGP0020D 3271.36,2328.27 r0 top
U9 "LP8860QVFPRQ1" VFP0032B_N 3375.94,649.68 r90 top
USER "SKRKAEE010" SW_SKRKAEE010 2722,2803 r90 top (schematic designator S3)
VBOOST "5000" Keystone5000 2210,815 r0 top (schematic designator TP5)
VDD "SML-P12PTT86" SML-P1_GREEN 1105,650 r180 top (schematic designator D7)
ZZ1 "This Assembly Note is for PCB labels only" AssemblyNoteLabel 225,3650 r0 top
ZZ2 "These assemblies are ESD sensitive, ESD precautions shall be observed." AssemblyNote 225,3550 r0 top
ZZ3 "These assemblies must be clean and free from flux and all contaminants. Use of no clean flux is not acceptable." AssemblyNote 225,3450 r0 top
ZZ4 "These assemblies must comply with workmanship standards IPC-A-610 Class 2., unless otherwise specified." AssemblyNote 225,3350 r0 top
ZZ5 "Controlled Impedance Layers: 2. Top and bottom layers 50 ohm impedance +/- 10% for 8 mil traces." AssemblyNote 225,3250 r0 top

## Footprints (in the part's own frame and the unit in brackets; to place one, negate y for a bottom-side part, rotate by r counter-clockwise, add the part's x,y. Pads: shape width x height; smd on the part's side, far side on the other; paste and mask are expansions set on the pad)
0402 [mm] "0402 from SM-752 data"
  rect 0.8x0.6 smd: 1(-0.6,0) 2(0.6,0)
  silkscreen extent -1.22,-0.52 1.22,0.52, body extent -0.55,-0.3 0.55,0.3, height 0.6
0603 [mm] "0603 from SM-752 data"
  rect 1x0.95 smd: 1(-0.8,0) 2(0.8,0)
  silkscreen extent -1.52,-0.69 1.52,0.69, body extent -0.87,-0.47 0.87,0.47, height 0.85
0805_HV [mil] "0805 with 30mil clearance between pads"
  rect 50x63 smd: 1(-40,0) 2(40,0)
  silkscreen extent -74,-40 74,40, body extent -43,-29 43,29, height 43
1206 [mm] "1206 from SM-752 data"
  rect 1.3x1.85 smd: 1(-1.45,0) 2(1.45,0)
  silkscreen extent -2.4,-1.21 2.4,1.21, body extent -1.7,-0.9 1.7,0.9, height 1.35
1210 [mm] "1210 from SM-752 data"
  rect 1.3x2.7 smd: 1(-1.45,0) 2(1.45,0)
  silkscreen extent -2.32,-1.57 2.32,1.57, body extent -1.7,-1.35 1.7,1.35, height 1.35
1210M [mm] "1210 from SM-752 data"
  rect 1.5x2.8 smd: 1(-1.55,0) 2(1.55,0)
  silkscreen extent -2.75,-1.85 2.75,1.85, body extent -1.7,-1.35 1.7,1.35, height 1.35
2220 [mm] "Chip Capacitor, Body 5.7x5.0mm, IPC Medium Density"
  rect 1.6x5.3 smd: 1(-2.6,0) 2(2.6,0)
  silkscreen extent -3.69,-2.94 3.69,2.94, body extent -2.95,-2.62 2.95,2.62, height 1.35
2412 [mm] "Ohmite recommended land pattern"
  rect 3.25x1.9 smd: 1(-2.625,-1.25) 2(2.625,-1.25) 3(-2.625,1.25) 4(2.625,1.25)
  silkscreen extent -0.67,-1.96 0.67,1.96, body extent -3.3,-1.71 3.3,1.71, height 0.7
2512M [mm] "Chip Resistor, Body 6.3x3.2mm, IPC Low Density"
  rect 1.5x3.5 smd: 1(-3.05,0) 2(3.05,0)
  silkscreen extent -1.9,-1.65 1.9,1.65, body extent -3.22,-1.67 3.22,1.67, height 0.71
AssemblyNote [mil] "Assembly Note"
AssemblyNoteLabel [mil] "Assembly Note for PCB Labels"
CAPSMT_62_HA0 [mm] "8 x 10mm:  Chemi-Con HA0"
  rect 4.2x2.2 smd: 1(-3.65,0) 2(3.65,0)
  silkscreen extent -4.25,-4.25 4.25,4.25, body extent -4.26,-4.26 4.26,4.26, height 10.5
CONN_851-43-006-20-001000 [mil] "Mill-Max"
  rect 36x70 hole 26: 1(125,0)
  oval 36x70 hole 26: 2(75,0) 3(25,0) 4(-25,0) 5(-75,0) 6(-125,0)
  silkscreen extent -160,-210 160,-50, body extent -157,-210 157,8, height 87
CONN_90120-0122 [mm] "Molex"
  rect 1.65x1.65 hole 1.016 mask+0: 1(-1.27,0)
  round 1.65 hole 1.016 mask+0: 2(1.27,0)
  silkscreen extent -3.56,-1.27 2.54,1.27, body extent -2.54,-1.27 2.54,1.27, height 9.29
CONN_PEC02SAAN [mm] "SULLINS"
  rect 1.5x1.5 hole 1.016: 1(-1.27,0)
  round 1.5 hole 1.016: 2(1.27,0)
  silkscreen extent -3.45,-1.27 2.54,1.27, body extent -2.54,-1.27 2.54,1.27, height 8.38
DGQ0010A_N [mm] "TSSOP, 10-Leads, Body 3x3mm, Pitch 0.5mm, Exposed Pad, IPC Medium Density"
  oval 1.7x0.3 smd: 1(-2.05,1) 2(-2.05,0.5) 3(-2.05,0) 4(-2.05,-0.5) 5(-2.05,-1) 6(2.05,-1) 7(2.05,-0.5) 8(2.05,0) 9(2.05,0.5) 10(2.05,1)
  rect 1.73x1.9 smd: 11(0,0)
  silkscreen extent -0.9,-1.55 0.9,1.55, body extent -2.45,-1.5 2.45,1.5, height 0.94
DPAK [mm] "D-PAK, 3-Pads, Body 6.22x6.73mm (max), TO-252AA using nominal STEP model"
  rect 2.6x1.6 smd: 1(-3.4,2.28) 3(-3.4,-2.28)
  rect 6.2x5.8 smd paste-2.9: 4(3.4,0)
  silkscreen extent -5,-3.5 6.83,3.5, body extent -3.86,-3.29 5.84,3.29, height 2.48
DS90UH926QSQ/NOPB [mm] "IC SERIAL/DESERIAL 24 BIT 60-LLP"
  rect 0.25x0.8 smd mask+0.05: 1(-3.5,-4.3) 2(-3,-4.3) 3(-2.5,-4.3) 4(-2,-4.3) 5(-1.5,-4.3) 6(-1,-4.3) 7(-0.5,-4.3) 8(0,-4.3) 9(0.5,-4.3) 10(1,-4.3) 11(1.5,-4.3) 12(2,-4.3) 13(2.5,-4.3) 14(3,-4.3) 15(3.5,-4.3) 31(3.5,4.3) 32(3,4.3) 33(2.5,4.3) 34(2,4.3) 35(1.5,4.3) 36(1,4.3) 37(0.5,4.3) 38(0,4.3) 39(-0.5,4.3) 40(-1,4.3) 41(-1.5,4.3) 42(-2,4.3) 43(-2.5,4.3) 44(-3,4.3) 45(-3.5,4.3)
  rect 0.8x0.25 smd mask+0.05: 16(4.3,-3.5) 17(4.3,-3) 18(4.3,-2.5) 19(4.3,-2) 20(4.3,-1.5) 21(4.3,-1) 22(4.3,-0.5) 23(4.3,0) 24(4.3,0.5) 25(4.3,1) 26(4.3,1.5) 27(4.3,2) 28(4.3,2.5) 29(4.3,3) 30(4.3,3.5) 46(-4.3,3.5) 47(-4.3,3) 48(-4.3,2.5) 49(-4.3,2) 50(-4.3,1.5) 51(-4.3,1) 52(-4.3,0.5) 53(-4.3,0) 54(-4.3,-0.5) 55(-4.3,-1) 56(-4.3,-1.5) 57(-4.3,-2) 58(-4.3,-2.5) 59(-4.3,-3) 60(-4.3,-3.5)
  rect 6.3x6.3 smd: 61(0,0)
  silkscreen extent -4.65,-5.25 4.65,4.65, body extent -4.55,-4.55 4.55,4.55, height 0.81
DSG0008A [mm] "SON, 8-Leads, Body 2x2mm, Pitch 0.5mm, Thermal Pad 1.6x0.9mm, TI Recommended"
  rect 0.5x0.25 smd paste-0.14 mask+0.07: 1(-0.95,0.75) 2(-0.95,0.25) 3(-0.95,-0.25) 4(-0.95,-0.75) 5(0.95,-0.75) 6(0.95,-0.25) 7(0.95,0.25) 8(0.95,0.75)
  rect 0.9x1.6 smd paste-0.45 mask+0.07: 9(0,0)
  silkscreen extent -1.07,1.15 -0.63,1.15, body extent -1.05,-1.05 1.05,1.05, height 0.8
Fiducial10-20 [mm]
  round 1 smd paste-0.5 mask+0.5: 1(0,0)
HDR-100_1X6 [mil]
  rect 70x70 hole 40: 1(0,0) 2(100,0) 3(200,0) 4(300,0) 5(400,0) 6(500,0)
  silkscreen extent -110,35 -70,75
IEC_HighVoltage_Small [mil]
  silkscreen extent -107,-88 107,97
IHLP-5050FD [mm] "Vishay Dale recommended land pattern.  Document 34123 rev 18-Sep-09"
  rect 2.945x4.95 smd: 1(-5.407,0) 2(5.407,0)
  silkscreen extent -6.6,-6.5 6.6,6.5, body extent -6.86,-6.45 6.86,6.45, height 6.5
IND_DLW21S [mm] "muRata"
  rect 0.4x0.9 smd: 1(-0.45,0.85) 2(-0.45,-0.85) 3(0.45,-0.85) 4(0.45,0.85)
  silkscreen extent -0.96,0.88 -0.92,0.92, body extent -0.7,-1.1 0.7,1.1, height 1.41
Keystone5000 [mil] "For Keystone 500x miniature loop terminals"
  round 80 hole 40: 1(0,0)
  silkscreen extent -58,-58 58,58, body extent -49,-49 49,49, height 182
Keystone5001 [mil] "For Keystone 500x miniature loop terminals"
  round 80 hole 40: 1(0,0)
  silkscreen extent -58,-58 58,58, body extent -49,-49 49,49, height 182
Keystone5004 [mil] "For Keystone 500x miniature loop terminals"
  round 80 hole 40: 1(0,0)
  silkscreen extent -58,-58 58,58, body extent -49,-49 49,49, height 182
LED_SMLP12_ORANGE [mm] "Rohm Semiconductor"
  rect 0.5x0.6 smd mask+0.08: 1(-0.45,0) 2(0.45,0)
  silkscreen extent 0.92,-0.3 0.92,0.3, body extent -0.55,-0.35 0.55,0.35, height 0.25
LED_SMLP12_Yellow [mm] "Rohm Semiconductor"
  rect 0.5x0.6 smd mask+0.08: 1(-0.45,0) 2(0.45,0)
  silkscreen extent 0.92,-0.3 0.92,0.3, body extent -0.55,-0.35 0.55,0.35, height 0.25
LPS4018 [mil]
  rect 28x123 smd: 1(-72.5,0) 2(72.5,0)
  rect 35.5x28 smd rot 45: 1(-64,64) 2(64.5,-63.5)
  rect 35.5x28 smd rot 135: 1(-64,-64) 2(64,64)
  rect 31.5x28 smd: 1(-46,72.5) 1(-46,-72.5) 2(46,72.5) 2(46,-72.5)
  silkscreen extent -100,-102 100,112, body extent -81,-81 81,81, height 71
Net-Tie_10mil [mil] "10mil net tie, no solder mask opening, no solder paste"
  rect 10x10 smd paste-5 mask-5: 1(-10,0) 2(10,0)
  Top Layer region: -6,5 6,5 6,-5 -6,-5
"NY PMS 440 0025 PH" [mm] "4-40 nylon screw and mounting hole"
  round 8 hole 3.2: 1(0,0)
  body extent -3.3,-3.3 3.3,3.3, height 2.69
PhoenixConact_1727010 [mm]
  rect 1.7x1.7 hole 1.1: 1(-1.905,0)
  round 1.7 hole 1.1: 2(1.905,0)
  silkscreen extent -4.8,-3.6 3.81,3.6, body extent -3.81,-3.6 3.81,3.7, height 8.52
PowerPAK_SO-8L [mm] "based on Vishay recommended land pattern Document 63818 Feb 7, 2012"
  rect 1x0.41 smd: 1(-2.805,1.905) 2(-2.805,0.635) 3(-2.805,-0.635) 4(-2.805,-1.905)
  rect 3.63x4.061 smd: 5(0.805,0)
  Top Layer region: -0.297,-2.64 0.298,-2.64 0.298,-2.03 -0.297,-2.03
  Top Layer region: -0.298,2.03 0.297,2.03 0.297,2.64 -0.298,2.64
  Top Layer region: 2.615,-2.5 3.125,-2.5 3.125,2.5 2.615,2.5
  body extent -3.07,-2.57 3.08,2.57, height 1.21
RGP0020D [mm] "QFN, 20-Leads, Body 4x4mm, Pitch 0.5mm, Thermal Pad 2.7x2.7mm, TI Recommended"
  oval 0.6x0.24 smd mask+0.07: 1(-1.9,1) 2(-1.9,0.5) 3(-1.9,0) 4(-1.9,-0.5) 5(-1.9,-1) 11(1.9,-1) 12(1.9,-0.5) 13(1.9,0) 14(1.9,0.5) 15(1.9,1)
  oval 0.24x0.6 smd mask+0.07: 6(-1,-1.9) 7(-0.5,-1.9) 8(0,-1.9) 9(0.5,-1.9) 10(1,-1.9) 16(1,1.9) 17(0.5,1.9) 18(0,1.9) 19(-0.5,1.9) 20(-1,1.9)
  rect 2.7x2.7 smd paste-1.35 mask+0.07: 21(0,0)
  silkscreen extent -2.22,1.54 -1.54,2.22, body extent -2.07,-2.07 2.07,2.07, height 1.01
RHA0040B [mm] "QFN, 40-Leads, Body 6x6mm, Pitch 0.5mm, Thermal Pad 4.15 x 4.15mm, TI Recommended"
  oval 0.6x0.23 smd mask+0.07: 1(-2.9,2.25) 2(-2.9,1.75) 3(-2.9,1.25) 4(-2.9,0.75) 5(-2.9,0.25) 6(-2.9,-0.25) 7(-2.9,-0.75) 8(-2.9,-1.25) 9(-2.9,-1.75) 10(-2.9,-2.25) 21(2.9,-2.25) 22(2.9,-1.75) 23(2.9,-1.25) 24(2.9,-0.75) 25(2.9,-0.25) 26(2.9,0.25) 27(2.9,0.75) 28(2.9,1.25) 29(2.9,1.75) 30(2.9,2.25)
  oval 0.23x0.6 smd mask+0.07: 11(-2.25,-2.9) 12(-1.75,-2.9) 13(-1.25,-2.9) 14(-0.75,-2.9) 15(-0.25,-2.9) 16(0.25,-2.9) 17(0.75,-2.9) 18(1.25,-2.9) 19(1.75,-2.9) 20(2.25,-2.9) 31(2.25,2.9) 32(1.75,2.9) 33(1.25,2.9) 34(0.75,2.9) 35(0.25,2.9) 36(-0.25,2.9) 37(-0.75,2.9) 38(-1.25,2.9) 39(-1.75,2.9) 40(-2.25,2.9)
  rect 4.15x4.15 smd paste-2.1 mask+0.07: 41(0,0)
  silkscreen extent -3.22,2.79 -2.79,3.22, body extent -3.08,-3.08 3.08,3.08, height 1.01
Rosenberger_D4S20G-400A5 [mm] "Rosenberger"
  rect 1.5x1.5 hole 1 paste+0: 1(-7.25,-1)
  round 1.5 hole 1 paste+0: 2(-5.25,-1) 3(-5.25,1) 4(-7.25,1)
  round 2.2 hole 1.7 paste+0: 5(-10.75,4.5) 6(-10.75,-4.5) 7(-1.75,-4.5) 8(-1.75,4.5)
  silkscreen extent -12.32,-6 14.83,6.95, body extent -12.32,-6 14.83,6, height 13.51
RSE0010A [mm] "QFN, 10-Leads, Body 1.5x2mm, Pitch 0.5mm, TI Recommended"
  rect 0.58x0.3 smd paste-0.025 mask+0.05: 1(-0.64,0.75) 2(-0.64,0.25) 3(-0.64,-0.25) 4(-0.64,-0.75) 6(0.64,-0.75) 7(0.64,-0.25) 8(0.64,0.25) 9(0.64,0.75)
  rect 0.35x0.63 smd paste-0.025 mask+0.05: 5(0,-0.86) 10(0,0.86)
  silkscreen extent -1.22,-1.17 0.77,1.22, body extent -0.77,-1.02 0.78,1.03, height 0.6
Samtec_QRM8-026-02.0-L-D-A [mm] "Samtec recommended land pattern"
  rect 0.5x1.5 smd mask+0.05: 1(-10,1.425) 2(-10,-1.425) 3(-9.2,1.425) 4(-9.2,-1.425) 5(-8.4,1.425) 6(-8.4,-1.425) 7(-7.6,1.425) 8(-7.6,-1.425) 9(-6.8,1.425) 10(-6.8,-1.425) 11(-6,1.425) 12(-6,-1.425) 13(-5.2,1.425) 14(-5.2,-1.425) 15(-4.4,1.425) 16(-4.4,-1.425) 17(-3.6,1.425) 18(-3.6,-1.425) 19(-2.8,1.425) 20(-2.8,-1.425) 21(-2,1.425) 22(-2,-1.425) 23(-1.2,1.425) 24(-1.2,-1.425) 25(-0.4,1.425) 26(-0.4,-1.425) 27(0.4,1.425) 28(0.4,-1.425) 29(1.2,1.425) 30(1.2,-1.425) 31(2,1.425) 32(2,-1.425) 33(2.8,1.425) 34(2.8,-1.425) 35(3.6,1.425) 36(3.6,-1.425) 37(4.4,1.425) 38(4.4,-1.425) 39(5.2,1.425) 40(5.2,-1.425) 41(6,1.425) 42(6,-1.425) 43(6.8,1.425) 44(6.8,-1.425) 45(7.6,1.425) 46(7.6,-1.425) 47(8.4,1.425) 48(8.4,-1.425) 49(9.2,1.425) 50(9.2,-1.425) 51(10,1.425) 52(10,-1.425)
  rect 4.6x0.51 smd mask+0.05: 53(-8.4,0) 54(-2.8,0) 55(2.8,0) 56(8.4,0)
  round 0 hole 1.13 unplated: 57(-11.85,-0.5) 58(11.85,-0.5)
  silkscreen extent -13.78,-2.8 13.78,2.8, body extent -13.27,-2.3 13.3,2.3, height 4.78
SLF10145 [mm]
  rect 2.5x3.2 smd: 1(-4.05,0) 2(4.05,0)
  silkscreen extent -5.66,-5.2 5.7,5.2, body extent -5.2,-5.2 5.2,5.2, height 4.8
SMB [mil] "Molded Diode, 2-Leads, Body 5.4x3.6mm, IPC Medium Density, based on OnSemi component dimensions"
  rect 85x107.99 smd: 1(-87.01,0) 2(87.01,0)
  silkscreen extent -155,-82 125,82, body extent -106,-71 106,71, height 91
SML-P1_GREEN [mm] "ROHM"
  rect 0.5x0.6 smd: 1(-0.45,0) 2(0.45,0)
  silkscreen extent -0.95,-0.3 -0.95,0.3, body extent -0.53,-0.33 0.53,0.33, height 0.25
SML-P1_YELLOW-GREEN [mm] "Rohm Semiconductor"
  rect 0.5x0.6 smd: 1(-0.45,0) 2(0.45,0)
  silkscreen extent -0.63,-0.61 1.33,0.61, body extent -0.55,-0.35 0.55,0.35, height 0.25
SOD-123 [mm] "On Semi recommended land pattern"
  rect 0.915x1.22 smd: 1(-1.637,0) 2(1.637,0)
  silkscreen extent -2.74,-1.17 2.03,1.17, body extent -1.93,-0.9 1.93,0.9, height 1.35
SW_219-3LPST [mm] "SW, Tape Seal, 3 POS, SMD"
  rect 2.44x1.12 smd: 1(-4.305,2.54) 2(-4.305,0) 3(-4.305,-2.54) 4(4.305,-2.54) 5(4.305,0) 6(4.305,2.54)
  silkscreen extent -3.35,-4.57 3.35,4.52, body extent -4.95,-4.55 4.96,4.54, height 4.25
SW_SKRKAEE010 [mm] "Alps recommended land pattern"
  rect 0.8x2 smd: 1(-2.1,0) 2(2.1,0)
  body extent -2.4,-1.45 2.4,1.45, height 1.96
TI_Horizontal_Overlay_Small [mil]
  silkscreen extent -545,-68 545,67
TO-277[SMPC] [mil]
  rect 55x50 smd: 1(42,-168.6) 2(-42,-168.6)
  rect 185x195 smd: 3(0,0)
TSW-102-07-G-S [mm] "Samtec 100mil, 1x2, 230 mil above insulator"
  rect 1.65x1.65 hole 1.016 mask+0: 1(-1.27,0)
  round 1.65 hole 1.016 mask+0: 2(1.27,0)
  silkscreen extent -3.56,-1.27 2.54,1.27, body extent -2.54,-1.27 2.54,1.27, height 8.38
VFP0032B_N [mm] "QFP, 32-Leads, Body 7x7mm, Pitch 0.8mm, Thermal Pad 5.5x5.5mm, IPC Normal Density"
  oval 1.65x0.55 smd mask+0.07: 1(-4.175,2.8) 2(-4.175,2) 3(-4.175,1.2) 4(-4.175,0.4) 5(-4.175,-0.4) 6(-4.175,-1.2) 7(-4.175,-2) 8(-4.175,-2.8) 17(4.175,-2.8) 18(4.175,-2) 19(4.175,-1.2) 20(4.175,-0.4) 21(4.175,0.4) 22(4.175,1.2) 23(4.175,2) 24(4.175,2.8)
  oval 0.55x1.65 smd mask+0.07: 9(-2.8,-4.175) 10(-2,-4.175) 11(-1.2,-4.175) 12(-0.4,-4.175) 13(0.4,-4.175) 14(1.2,-4.175) 15(2,-4.175) 16(2.8,-4.175) 25(2.8,4.175) 26(2,4.175) 27(1.2,4.175) 28(0.4,4.175) 29(-0.4,4.175) 30(-1.2,4.175) 31(-2,4.175) 32(-2.8,4.175)
  rect 5.5x5.5 smd paste-0.81 mask-0.8: 33(0,0)
  silkscreen extent -4.19,3.56 -3.94,3.81, body extent -3.5,-3.5 3.5,3.5, height 1.61

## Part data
C1: "CAP, CERM, 22uF, 16V, +/-20%, X7R, 1210"
C2 C7 C8 C10 C14 C20 C21 C47 C48: "CAP, CERM, 0.1uF, 50V, +/-10%, X7R, 0603"
C3 C80: "CAP, CERM, 0.1uF, 250V, +/-10%, X7R, 1206"
C4 C5 C16 C17 C68 C69 C78 C79: "CAP, CERM, 0.047uF, 16V, +/-10%, X7R, 0402"
C6 C9 C27 C33 C36 C38 C39 C43 C56 C75 C77: "CAP, CERM, 0.1uF, 16V, +/-5%, X7R, 0603"
C11 C44: "CAP, CERM, 4.7uF, 16V, +/-10%, X5R, 0805"
C12 C15 C24 C29 C32 C34 C37 C40 C41: "CAP, CERM, 4.7uF, 10V, +/-10%, X7R, 0805"
C18: "CAP, CERM, 10uF, 50V, +/-20%, X7R, 2220"
C19 C22 C71 C73: "CAP, CERM, 0.1uF, 16V, +/-10%, X5R, 0402"
C23 C26 C28 C58 C64 C66: "CAP, CERM, 0.1uF, 100V, +/-10%, X7R, 1206"
C25 C60: "CAP, CERM, 2.2uF, 16V, +/-10%, X7R, 0805"
C30 C31 C35 C45 C49 C51 C54 C57: "CAP, CERM, 10uF, 100V, +/-20%, X7S, 2220"
C42 C74: "CAP, AL, 47uF, 63V, +/-20%, 0.7 ohm, SMD"
C46: "CAP, CERM, 220pF, 50V, +/-5%, C0G/NP0, 0603"
C50 C55: library part Capacitor, "CAP CER 2200PF 50V 10% X7R 0402"
C52 C65 C70: "CAP, CERM, 10uF, 10V, +/-10%, X7R, 0805"
C53 C59 C61: "CAP, CERM, 0.1uF, 10V, +/-10%, X5R, 0402"
C62: "CAP, CERM, 47pF, 100V, +/-5%, C0G/NP0, 0603"
C63: "CAP, CERM, 10uF, 16V, +/-10%, X5R, 0805"
C67: "CAP, CERM, 1000pF, 100V, +/-10%, X7R, 0603"
C72 C76: "CAP, CERM, 1uF, 25V, +/-10%, X7R, 0603"
C81 C82 C83 C84: "CAP, CERM, 2200pF, 100V, +/-5%, X7R, 0603"
C85: "CAP, CERM, 4700pF, 25V, +/-5%, C0G/NP0, 0603"
C86: "CAP, CERM, 0.039uF, 16V, +/-10%, X7R, 0603"
D1: "Diode, Schottky, 40V, 1A, SOD-123"
D2: "Diode, Schottky, 60V, 2A, SMB"
D3: "Diode, High Current, Schottky Barrier, 5A, 100V"
D4: "LED, Yellow/green, SMD"
D5: "LED, Yellow, SMD"
D6: "LED, Orange, SMD"
D8 VDD: "LED, Green, SMD"
FID1 FID2 FID3 FID4 FID5 FID6: "Fiducial mark.  There is nothing to buy or mount."
H1 H2 H3: "Machine Screw, Round, #4-40 x 1/4, Nylon, Philips panhead"
ISET SW TP1 TP3 VBOOST: "Test Point, Miniature, Red, TH"
J1: "RIGHT ANGLE PLUG FOR PCB"
J2 J3 J7: "Conn Term Block, 2POS, 3.81mm PCB"
J4 J8: "Header, 100mil, 2x1, Tin plated, TH"
J5 J6: "Header, TH, 100mil, 2x1, Gold plated, 230 mil above insulator"
J9: "Header, 6 pin, 100mil Space, Gold Tail"
J10: "Receptacle, 50mil, 6x1, R/A, TH"
J11: "Slim body GND plane Socket 2x26, 2mm body height, Ag on contact, Alignment, SMD"
L1: "Inductor, Shielded, Ferrite, 5.6uH, 3.8A, 0.0264 ohm, SMD"
L2 L7: "Inductor, Shielded Drum Core, Ferrite, 3.3uH, 1.9A, 0.08 ohm, SMD"
L3: "Coupled inductor, 0.28A, 0.41 ohm, +/-25%, SMD"
L4 L5: "3A Ferrite Bead, 120 ohm @ 100MHz, SMD"
L6: "Inductor, Shielded, Powdered Iron, 22uH, 5.5A, 0.0313 ohm, SMD"
LOCK MCLK PASS SCL SDA TP2: "Test Point, Miniature, Yellow, TH"
LOGO1 LOGO3 LOGO4: library part IEC_HighVoltage, "IEC 61010-1 High Voltage Warning"
Logo2: library part TI_Logo, "Texas Instrument Corporate Signature"
NT1 NT2 NT3 NT4: "Single point connection between nets."
Q1: "MOSFET, P-CH, -60V, 30A, PowerPAK_SO-8L"
Q2: "MOSFET, N-CH, 60V, 25A, DPAK"
R1: "RES, 0 ohm, 5%, 0.25W, 1210"
R2 R83 R84 R85 R86 R87 R88 R89 R90 R91 R92 R93 R94 R95 R96 R97 R98 R99 R100 R101 R102 R103 R104 R105 R106: "RES, 49.9 ohm, 1%, 0.063W, 0402"
R3: "RES, 5.1k ohm, 5%, 0.1W, 0603"
R4: "RES, 1.6k ohm, 5%, 0.1W, 0603"
R5 R77 R78 R81 R111 R113 R114: "RES, 10k ohm, 5%, 0.1W, 0603"
R6 R7 R71 R72: "RES, 6.49k ohm, 1%, 0.063W, 0402"
R8 R12 R13 R15 R23 R24 R44 R55 R58 R59 R69 R80 R112: "RES, 0 ohm, 5%, 0.1W, 0603"
R9 R22 R61 R74: "RES, 13k ohm, 5%, 0.1W, 0603"
R10 R16 R65 R73: "RES, 2.7k ohm, 5%, 0.063W, 0402"
R11: "RES, 36k ohm, 5%, 0.1W, 0603"
R14 R17 R18 R63 R64 R70: "RES, 3.3k ohm, 5%, 0.063W, 0402"
R19 R33 R42 R43 R48 R51 R54 R56 R60 R109 R110: "RES, 10k ohm, 5%, 0.063W, 0402"
R20: "RES, 0.12 ohm, 5%, 0.25W, 1210"
R21 R62: "RES, 768k ohm, 1%, 0.063W, 0402"
R25: "RES, 18.0k ohm, 1%, 0.1W, 0603"
R26: "RES, 15.4k ohm, 1%, 0.1W, 0603"
R27: "RES, 9.09k ohm, 1%, 0.1W, 0603"
R28: "RES, 24.3k ohm, 1%, 0.1W, 0603"
R29: "RES, 0.02 ohm, 1%, 1W, 2412"
R30: "RES, 40.2k ohm, 1%, 0.125W, 0805"
R31: "RES, 20.0k ohm, 1%, 0.1W, 0603"
R32: "RES, 200 ohm, 1%, 0.1W, 0603"
R34 R40: "RES, 100 ohm, 1%, 0.1W, 0603"
R35: "RES, 47k ohm, 5%, 0.1W, 0603"
R36 R37 R38 R39 R47 R50: "RES, 33k ohm, 5%, 0.063W, 0402"
R41 R49: "RES, 47k ohm, 5%, 0.063W, 0402"
R45 R46 R53: "RES, 330 ohm, 5%, 0.063W, 0402"
R52: "RES, 0.025 ohm, 1%, 3W, 2512"
R57: "RES, 10.0 ohm, 1%, 0.1W, 0603"
R66 R68: "RES, 487 ohm, 1%, 0.063W, 0402"
R67 R107 R108: "RES, 220 ohm, 5%, 0.063W, 0402"
R75: "RES, 12.4k ohm, 1%, 0.1W, 0603"
R76: "RES, 3.0k ohm, 5%, 0.063W, 0402"
R79: "RES, 2.00Meg ohm, 1%, 0.1W, 0603"
R82: "RES, 750k ohm, 1%, 0.1W, 0603"
RESET USER: "Switch, Push Button, SMD"
RT1: "Thermistor NTC, 1.0k ohm, 5%, 0805"
S1: "Switch, Slide, SPST 3 poles, SMT"
TP11 TP12 TP13: "Test Point, Miniature, Black, TH"
U1: "42V 2A Constant On-Time Switching Regulator With Adjustable Current Limit, DGQ0010A"
U2 U8: "Piezo Haptic Driver with Boost, Digital Front End, and Internal Waveform Memory, RGP0020D"
U3: "IC SERIAL/DESERIAL 24 BIT 60-LLP"
U4 U6: "Automotive Catalog ESD Protected, High-Speed USB 2.0 (480-Mbps) 1:2 Multiplexer / Demultiplexer Switch, 16 ohm RON, 2.5 to 3.3V, -40 to 125 degC, 10-Pin UQFN (RSE), Green (RoHS & no Sb/Br)"
U5: "Single Channel, Ultra-Low Resistance Load Switch, DSG0008A"
U7: "Mixed Signal MicroController, RHA0040B"
U9: "LOW EMI, High Performance 4-Channel LED Driver for Automotive Lighting, VFP0032B"
ZZ1: library part AssemblyNoteLabel
ZZ2 ZZ3 ZZ4 ZZ5: library part AssemblyNote

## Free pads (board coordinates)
  round 236.22 hole 125: 0(250,2850) 0(1085,435) 0(3700,2850)

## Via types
v1: diameter 28, hole 12, Top Layer to Bottom Layer, 528 vias
v2: diameter 19.68, hole 7.87, Top Layer to Bottom Layer, 44 vias
v3: diameter 23.62, hole 11.81, Top Layer to Bottom Layer, 25 vias
v4: diameter 19.68, hole 7.87, Top Layer to Bottom Layer, tented both sides, 20 vias
v5: diameter 18.75, hole 7.87, Top Layer to Bottom Layer, 4 vias

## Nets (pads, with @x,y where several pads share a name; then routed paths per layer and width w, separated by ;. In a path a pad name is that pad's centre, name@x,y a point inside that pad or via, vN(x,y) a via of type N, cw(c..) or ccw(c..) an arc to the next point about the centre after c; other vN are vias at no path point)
AV0000: R30.2 S1.6 | length 122.1
  Top Layer w8: S1.6@1355,2585.51 1355,2530 1395,2490 R30.2@1405,2490
AV0901: R27.2 R28.1 S1.5 | length 179
  Top Layer w8: R27.2@1255,2476.5 S1.5@1255,2585.51 ; R27.2@1255,2481.5 R28.1@1325,2481.5
AV1775: R25.2 R26.1 S1.4 | length 186.4
  Top Layer w8: R25.2@1115,2481.5 R26.1@1185,2481.5 1185,2530 1155,2560 S1.4@1155,2585.51
BISTC: R43.2 U3.16 U7.15 | length 1573.8
  Top Layer w8: U3.16@1340.65,1615.22 1359.78,1615.22 1370,1605 v1(1370,1565) ; R43.2@2513.62,1730 v1(2558.43,1730) 2570,1730 2629.16,1670.84 U7.15@2694.83,1670.84
  Inner Routing w8: v1(1370,1565) 1415.55,1519.45 1614.45,1519.45 1731,1636 1971.79,1636 2008.09,1672.3 2500.73,1672.3 v1(2558.43,1730)
BISTEN: R54.2 U3.44 U7.28 | length 4241.2
  Top Layer w8: v1(1010,1980) 1030,1980 1053.24,1956.76 U3.44@1053.24,1922.3 ; R54.2@2858.21,1460.41 U7.28@2858.21,1546.83 ; R54.2@2860,1448.62 2886.38,1448.62 2900,1435 v1(2900,1370)
  Inner Routing w8: v1(1010,1980) 984.25,1980 960,2004.25 960,2060 910,2110 730,2110 655,2035 655,1898.28 705,1848.28 705,1040.75 800.75,945 1115,945 1270,1100 2730,1100 2890,1260 2890,1360 v1(2900,1370)
BL_PWM: J11.6 U7.31 U9.18 | length 2780.8
  Top Layer w8: U7.31@2923.17,1572.42 2923.17,1541.83 v1(2965,1500) ; U9.18@3454.69,814.06 3454.69,854.68 v1(3480,880)
  Inner Routing w8: v1(2255,2230) 2255,1850 2285,1820 2550,1820 2605,1765 2605,1640 2710,1535 2930,1535 v1(2965,1500)
  Bottom Layer w8: J11.6@2106.1,2268.71 2216.29,2268.71 v1(2255,2230) ; v1(2965,1500) 3045,1500 3150,1395 3150,1325 3115,1290 3115,1230 3155,1190 3155,865 3180,840 3440,840 v1(3480,880)
BLU0: J11.50 R86.2 | length 851.2
  Bottom Layer w8: R86.2@1623.62,1580 1770,1580 1921.5,1428.5 2150.06,1428.5 2214.88,1493.32 2214.88,1540.12 2179.2,1575.8 J11.50@2106.1,1575.8
BLU1: J11.48 R87.2 | length 916.4
  Bottom Layer w8: R87.2@1623.62,1535 1793.08,1535 1915.08,1413 2156.48,1413 2230.38,1486.9 2230.38,1579.62 2202.71,1607.29 J11.48@2106.1,1607.29
BLU2: J11.46 R88.2 | length 969.8
  Bottom Layer w8: R88.2@1623.62,1490 1816.16,1490 1908.66,1397.5 2162.9,1397.5 2245.88,1480.48 2245.88,1599.12 2206.21,1638.79 J11.46@2106.1,1638.79
BLU3: J11.44 R95.2 | length 1285.2
  Bottom Layer w8: R95.2@1376.81,1500 1400,1500 1445,1455 1829.24,1455 1902.24,1382 2169.32,1382 2261.38,1474.06 2261.38,1605.54 2196.64,1670.28 J11.44@2106.1,1670.28
BLU4: J11.40 R96.2 | length 1371.9
  Bottom Layer w8: R96.2@1376.81,1455 1400,1455 1420,1435 1827.32,1435 1895.82,1366.5 2175.74,1366.5 2278.08,1468.84 2278.08,1656.92 2270.25,1664.75 ; J11.40@2106.1,1733.28 2201.47,1733.28 2270.13,1664.62
BLU5: J11.38 R97.2 | length 1435.2
  Bottom Layer w8: R97.2@1376.81,1410 1381.81,1415 1825.4,1415 1889.4,1351 2182.16,1351 2293.62,1462.46 2293.62,1686.38 ; J11.38@2106.1,1764.77 2214.98,1764.77 2293.37,1686.38
BLU6: J11.36 R98.2 | length 1530.8
  Bottom Layer w7.8: 2309.37,1715.63 2309.37,1485.35 2309.72,1485
  Bottom Layer w8: R98.2@1376.81,1365 1410,1365 1425,1350 1550,1350 1598,1398 1820.48,1398 1882.98,1335.5 2188.58,1335.5 2309.37,1456.29 2309.37,1485.35 ; J11.36@2106.1,1796.27 2228.48,1796.27 2309.12,1715.63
